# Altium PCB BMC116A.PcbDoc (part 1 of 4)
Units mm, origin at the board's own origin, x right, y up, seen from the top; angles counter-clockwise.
Board outline 154.94 x 104.14 mm, 6 copper layers (Top Layer, Signal Layer 1, Signal Layer 2, Signal Layer 3, Signal Layer 4, Bottom Layer), stack 1.56 mm thick; 252 components, 114 nets, 652 pads, 2530 vias.
Unrouted connection lines stored in the file: 13.
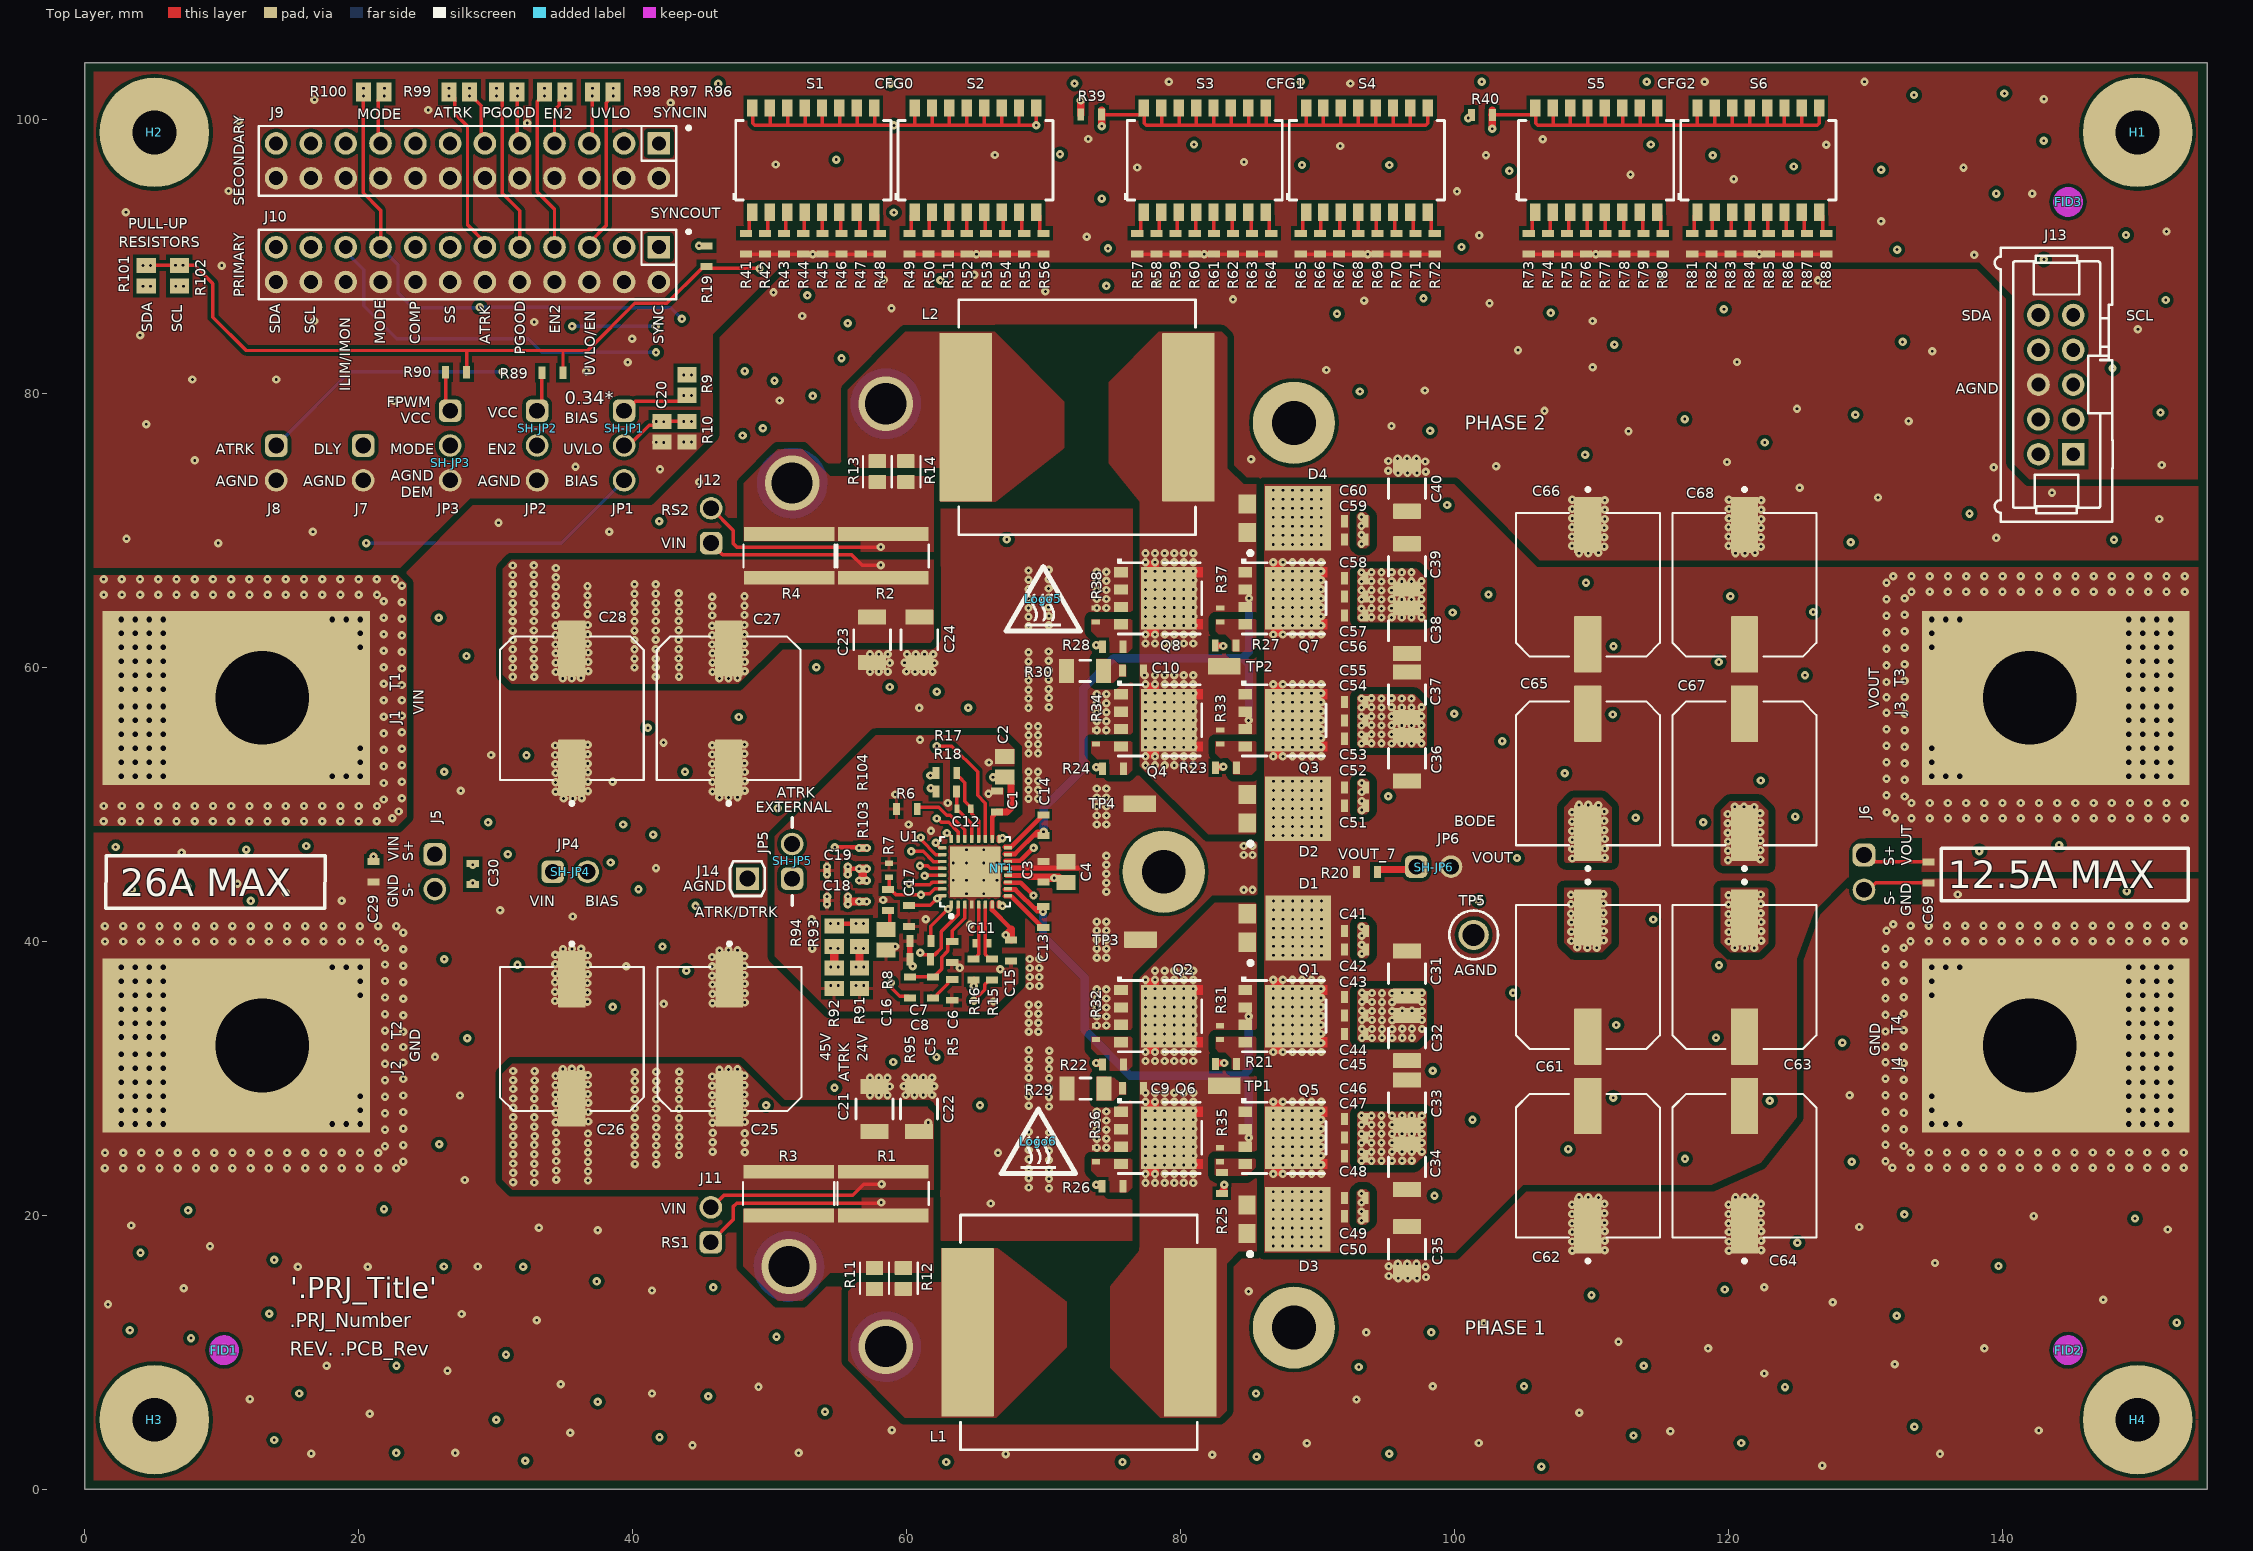
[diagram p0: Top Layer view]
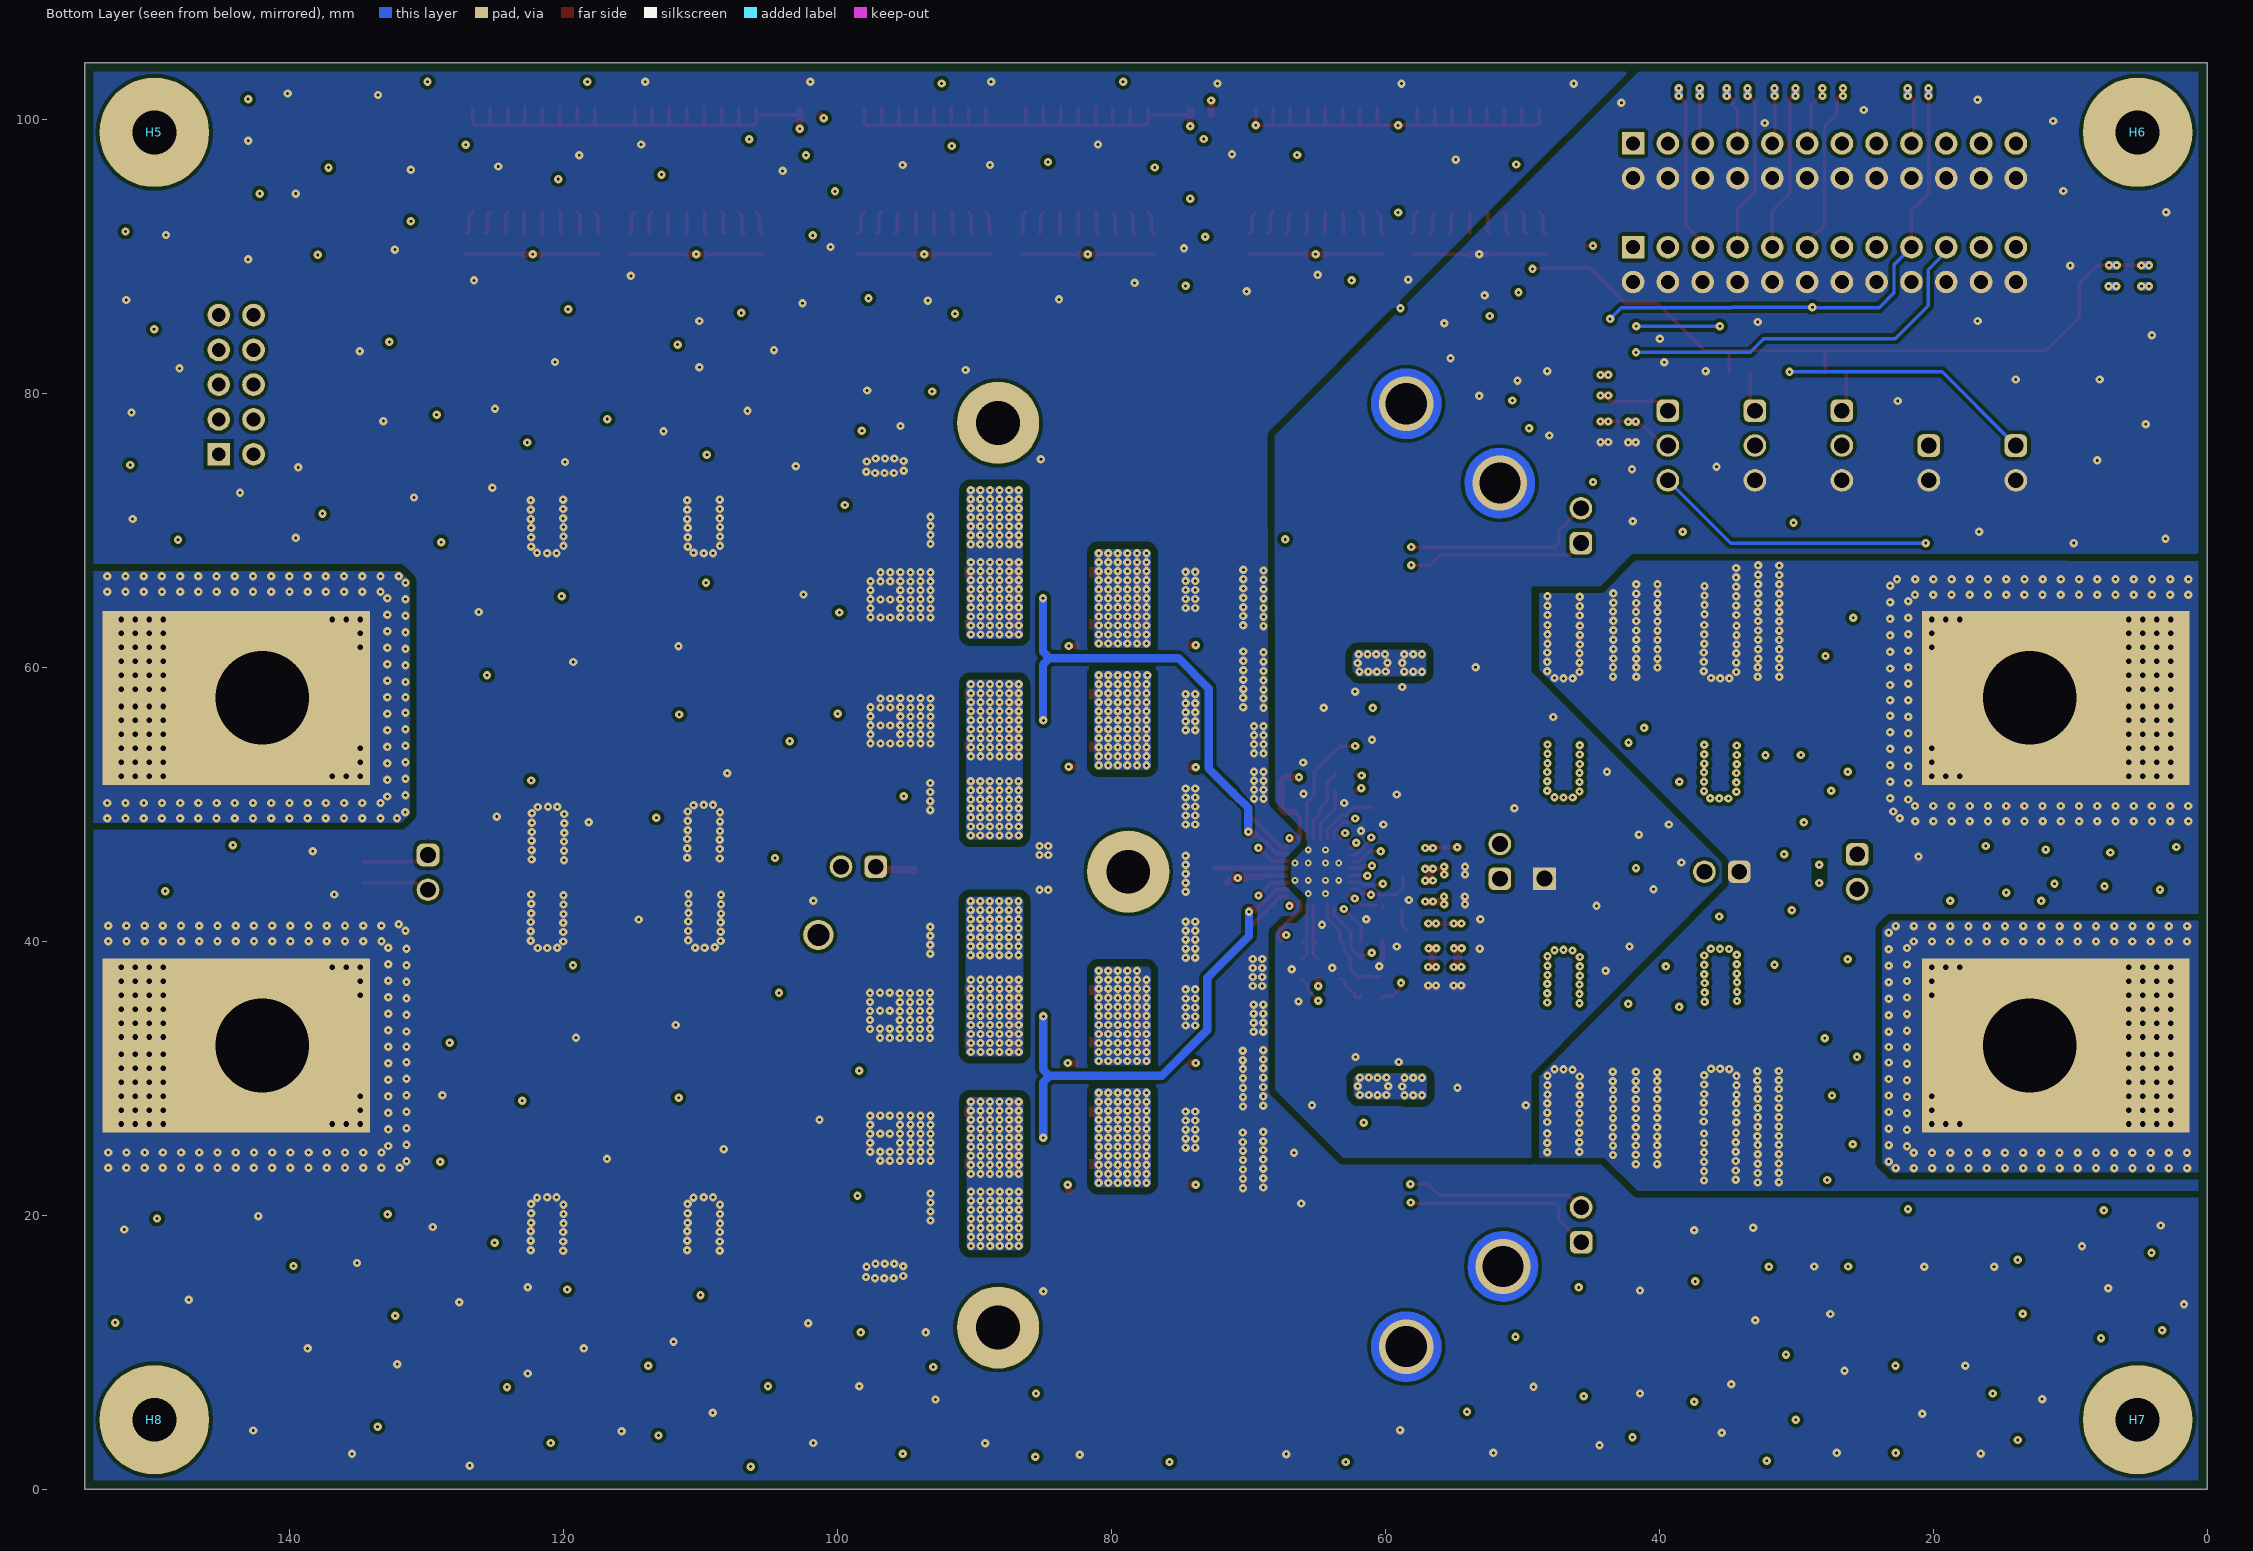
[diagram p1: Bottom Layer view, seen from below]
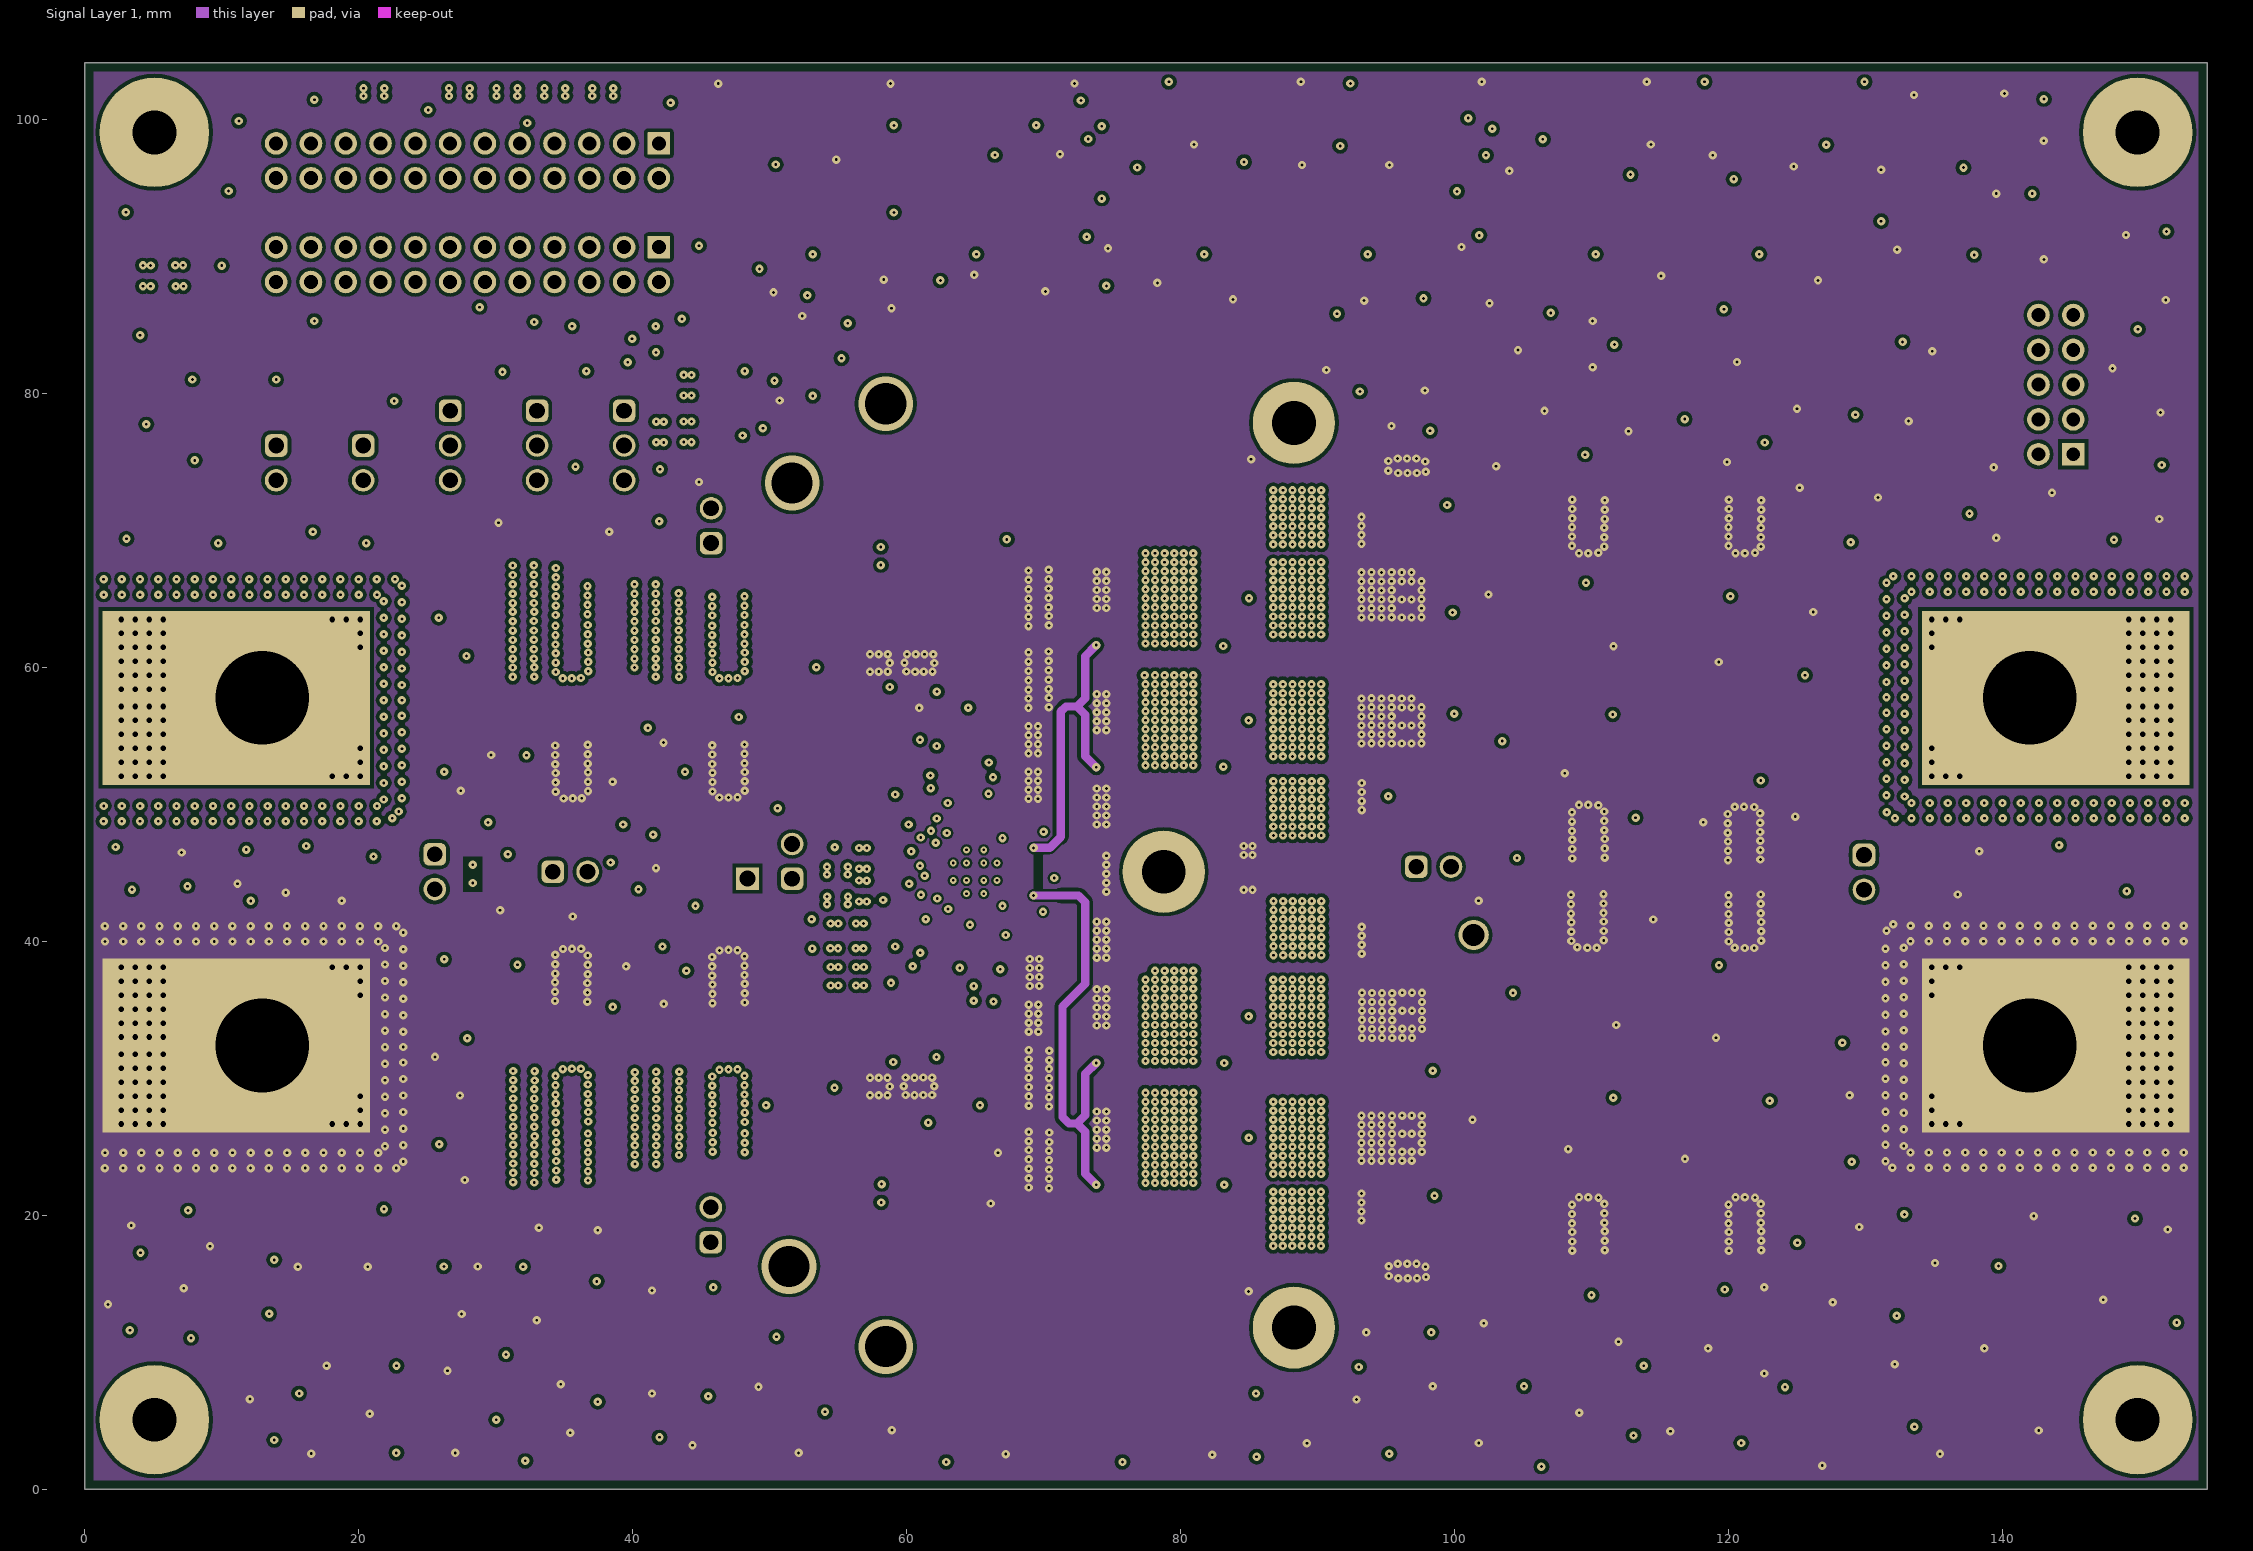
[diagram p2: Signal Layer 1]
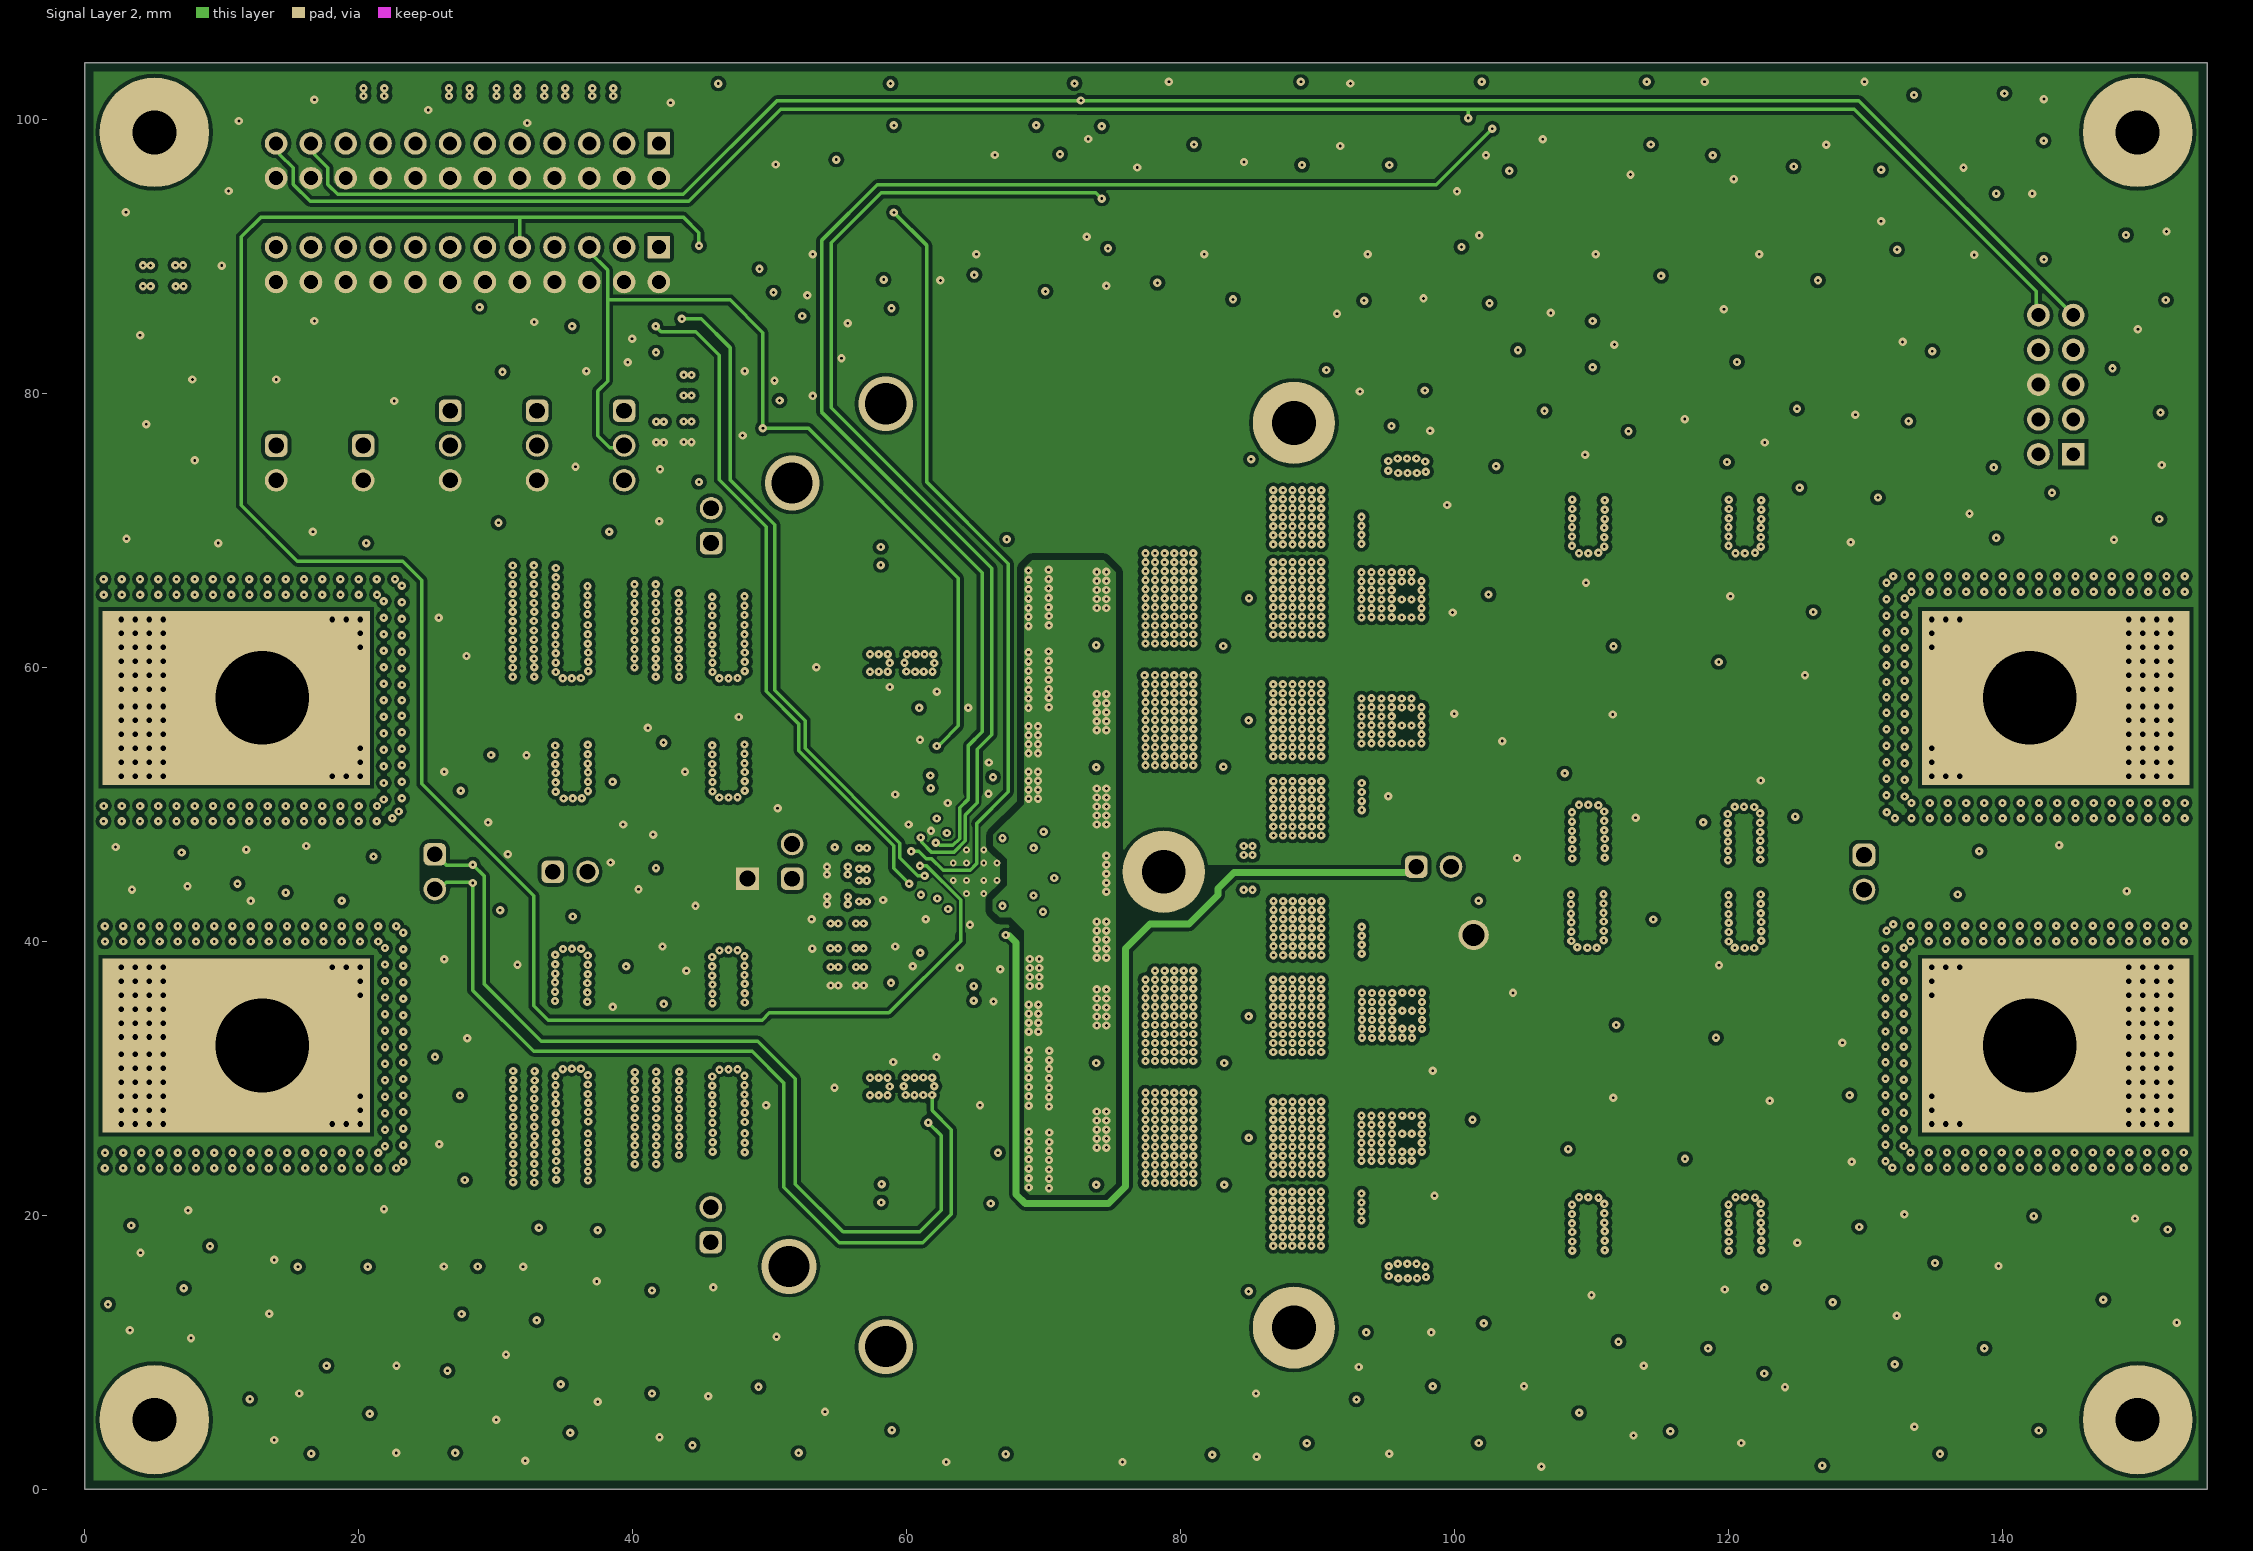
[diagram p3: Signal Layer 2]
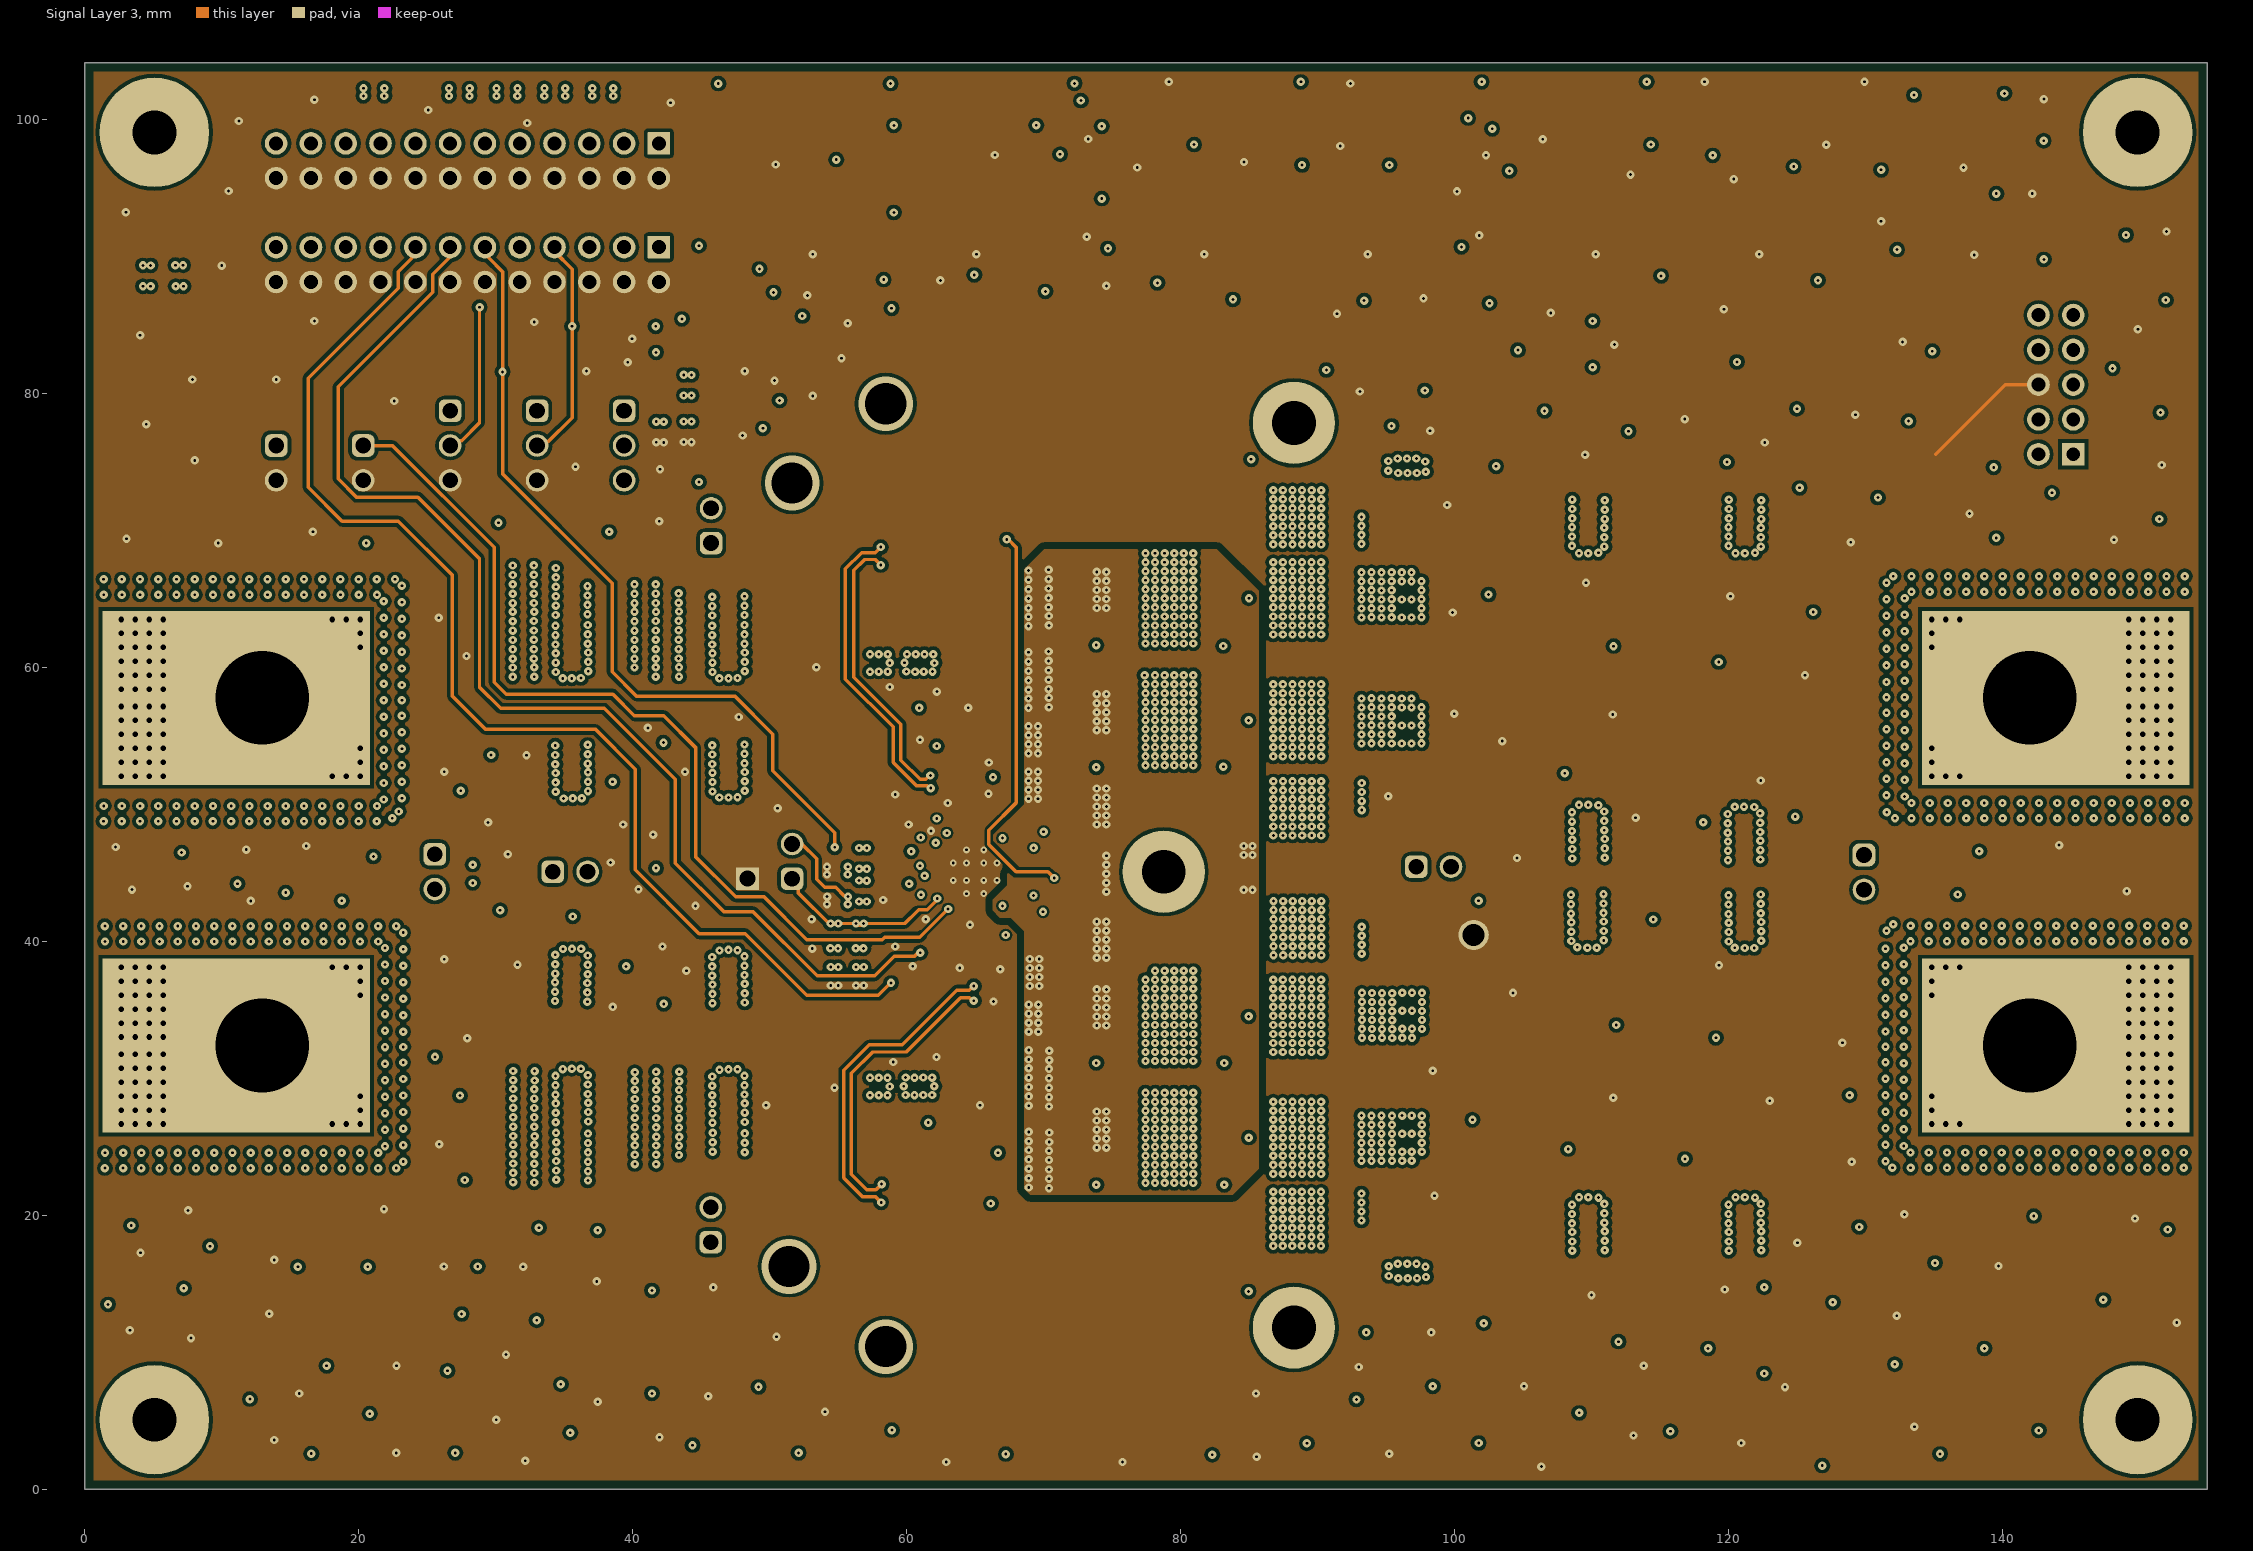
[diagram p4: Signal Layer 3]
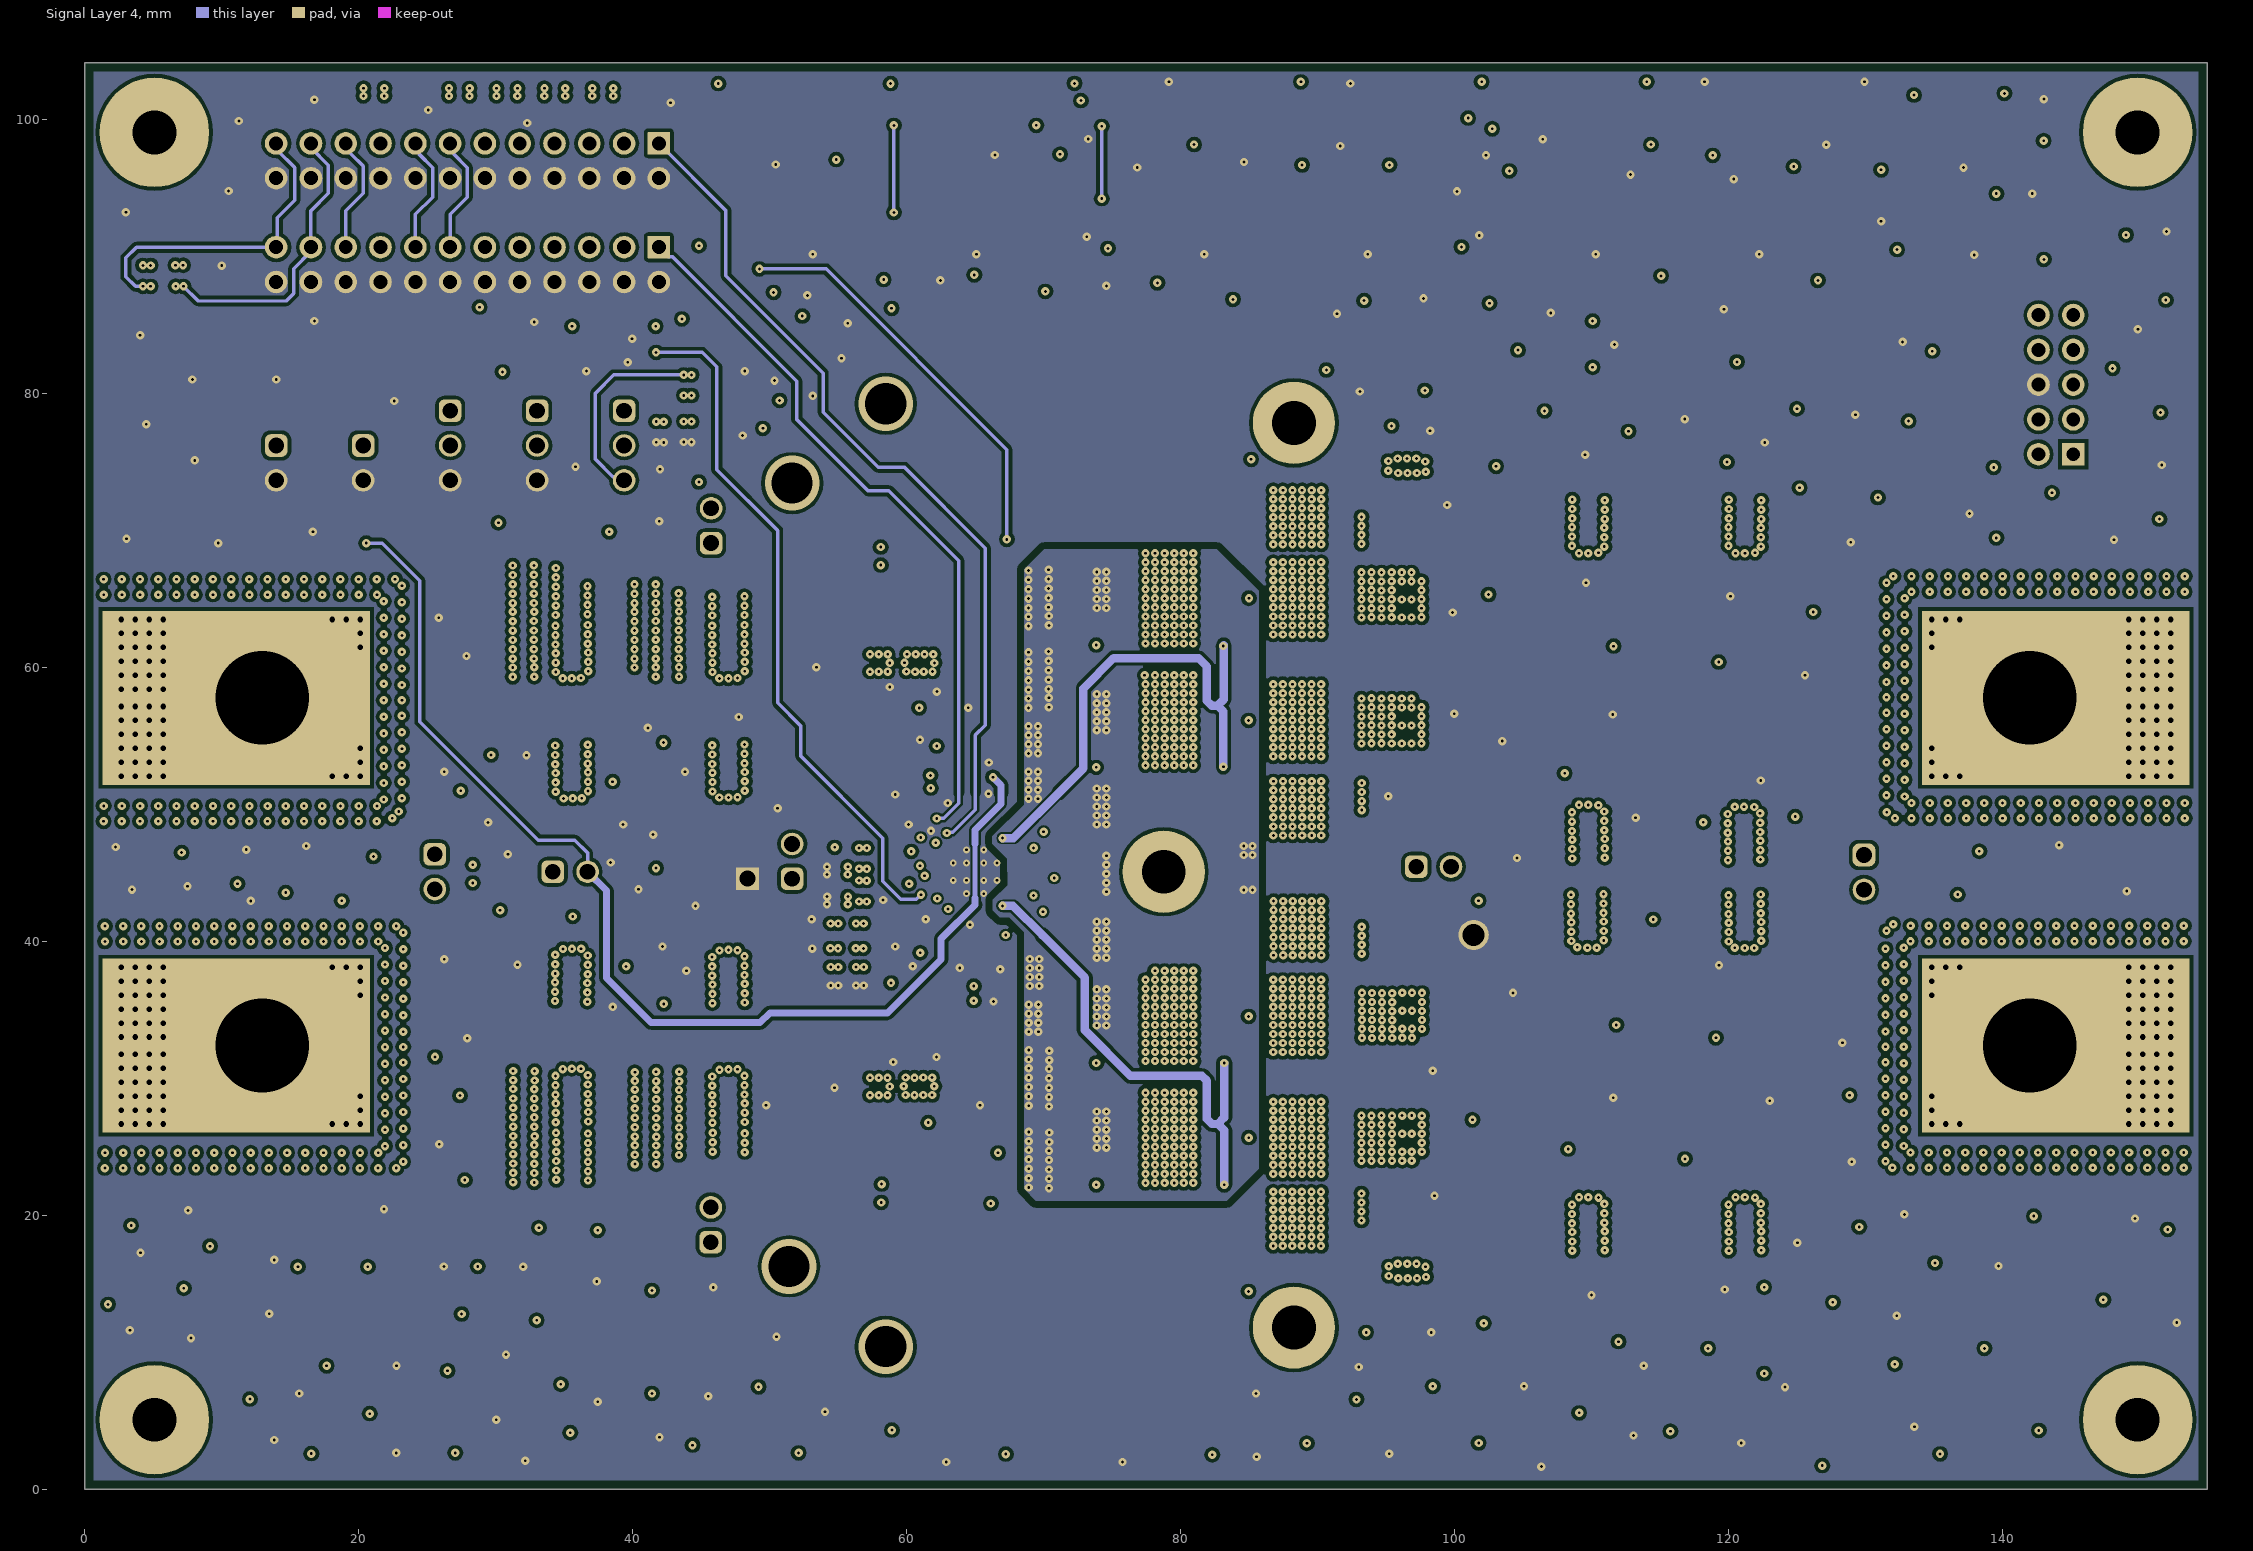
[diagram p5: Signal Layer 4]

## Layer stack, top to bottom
Top Solder: solder mask 0.0127, Solder Resist, Dk 3.5
Top Layer: signal copper 0.0711
Dielectric 1: prepreg 0.1778, FR-4 High Tg, Dk 4.2
Signal Layer 1: signal copper 0.0356
Dielectric 2: core 0.3556, FR-4 High Tg, Dk 4.2
Signal Layer 2: signal copper 0.0356
Dielectric 4: prepreg 0.2083, FR-4 High Tg, Dk 4.2
Signal Layer 3: signal copper 0.0356
Dielectric 5: core 0.3556, FR-4 High Tg, Dk 4.2
Signal Layer 4: signal copper 0.0356
Dielectric 3: prepreg 0.1778, FR-4 High Tg, Dk 4.2
Bottom Layer: signal copper 0.0711
Bottom Solder: solder mask 0.0127, Solder Resist, Dk 3.5

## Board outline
0,0 154.94,0 154.94,104.14 0,104.14

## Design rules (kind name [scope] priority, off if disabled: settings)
AcuteAngle [All] p1: minimum=4.50000000000000E+0001 checktracksonly=FALSE
AssemblyTestPointUsage [All] p1: valid=2
BoardOutlineClearance BoardOutlineClearance_MountingHoles [OnCopper and InComponentClass('Mounting Holes')] p1: gap=1 ignorepadtopadclearanceinfootprint=FALSE
BoardOutlineClearance BoardOutlineClearance_Poly [OnCopper and IsPoly] p2: gap=0.635 ignorepadtopadclearanceinfootprint=FALSE
BoardOutlineClearance [OnCopper and Not InComponentClass('Logo') and not InComponentClass('FiducialMark') and not InRegion(1000,500,4000,800) and not InPoly] p3: gap=1.016 ignorepadtopadclearanceinfootprint=FALSE
Clearance Clearance_IC [WithinRoom('IC_Room')] p1: gap=0.152 ignorepadtopadclearanceinfootprint=TRUE
Clearance Clearance_Keepouts [((IsTrack Or IsArc) And Not InPoly) And IsFree and IsKeepOut vs ((IsTrack Or IsArc) And Not InPoly) And IsFree and IsKeepOut] p2: gap=0 ignorepadtopadclearanceinfootprint=FALSE
Clearance Clearance_Poly [InPolygon] p3: gap=0.254 ignorepadtopadclearanceinfootprint=TRUE except(0.508: Poly-Poly)
Clearance Clearance_FiducialMark [IsKeepOut and InComponentClass('FiducialMark') vs IsPad and InComponentClass('FiducialMark')] p4: gap=0 ignorepadtopadclearanceinfootprint=FALSE
Clearance [All] p5: gap=0.2 ignorepadtopadclearanceinfootprint=TRUE
ComponentClearance ComponentClearance_Banana [HasFootprint('Johnson_108-0740-001') vs HasFootprint('Panduit_CXS70-14-C')] p1: gap=-1 collisioncheckmode=3 verticalgap=0 showdistances=FALSE
ComponentClearance ComponentClearance_JP_Res [InComponent('JP6') or InComponent('JP7') or InComponent('R1') or InComponent('R2') or InComponent('R3') or InComponent('R4') or InComponent('R11') or InComponent('R13') or InComponent('J11') or InComponent('J12') or  InComponent('J27') or InComponent('J28')] p2: gap=0 collisioncheckmode=3 verticalgap=0 showdistances=FALSE
ComponentClearance ComponentClearance_NT [InComponent('U1') or InComponent('NT1')] p3: gap=-1 collisioncheckmode=3 verticalgap=0 showdistances=FALSE
ComponentClearance ComponentClearance_MountingHoles_FiducialMarks [InComponentClass('Mounting Holes') vs InComponentClass('FiducialMark')] p4: gap=1.27 collisioncheckmode=3 verticalgap=0.254 showdistances=FALSE
ComponentClearance ComponentClearance_Shunt [InComponentClass('Header') vs InComponentClass('Shunt') or InComponent('SH-JP1') or InComponent('SH-JP2') or InComponent('SH-JP3') or InComponent('SH-JP4') or InComponent('SH-JP5') or InComponent('SH-JP6') or  InComponent('SH-JP8')  or  InComponent('SH-JP9')] p5: gap=0 collisioncheckmode=3 verticalgap=0 showdistances=FALSE
ComponentClearance ComponentClearance_Logo [InComponentClass('Logo')] p6: gap=0.762 collisioncheckmode=3 verticalgap=0.254 showdistances=FALSE
ComponentClearance ComponentClearance_ScrewToNut [(HasFootprint('NY PMS 440 0025 PH')) vs (HasFootprint('Keystone_1902C'))] p7: gap=0.127 collisioncheckmode=3 verticalgap=0.254 showdistances=FALSE
ComponentClearance ComponentClearance_MountingHoles [InComponentClass('Mounting Holes')] p8: gap=2.54 collisioncheckmode=3 verticalgap=2540 showdistances=FALSE
ComponentClearance ComponentClearance_SmallPassives [HasFootprint('0201*') or HasFootprint('0402*') or HasFootprint('0508') or HasFootprint('0603*') or HasFootprint('0612') or HasFootprint('0805*') or HasFootprint('0815*') or HasFootprint('0830*') or HasFootprint('1206*') or HasFootprint('1210*') or HasFootprint('1808*') or HasFootprint('1812*') or HasFootprint('1825*') or HasFootprint('2010*') or HasFootprint('2220*') or HasFootprint('2225*') or HasFootprint('2512*') or HasFootprint('2728*') or HasFootprint('3518*') vs HasFootprint('0201*') or HasFootprint('0402*') or HasFootprint('0508') or HasFootprint('0603*') or HasFootprint('0612') or HasFootprint('0805*') or HasFootprint('0815*') or HasFootprint('0830*') or HasFootprint('1206*') or HasFootprint('1210*') or HasFootprint('1808*') or HasFootprint('1812*') or HasFootprint('1825*') or HasFootprint('2010*') or HasFootprint('2220*') or HasFootprint('2225*') or HasFootprint('2512*') or HasFootprint('2728*') or HasFootprint('3518*')] p9: gap=0.38 collisioncheckmode=3 verticalgap=0.254 showdistances=FALSE
ComponentClearance ComponentClearance_THtoSMT [IsThruComponent vs IsSMTComponent] p10: gap=0.762 collisioncheckmode=3 verticalgap=0.762 showdistances=FALSE
ComponentClearance ComponentClearance_THtoTH [IsThruComponent vs IsThruComponent] p11: gap=0.508 collisioncheckmode=3 verticalgap=0.762 showdistances=FALSE
ComponentClearance [All] p12: gap=0.381 collisioncheckmode=3 verticalgap=0.254 showdistances=FALSE
DiffPairsRouting [All] p1: maxlimit=2.54 minlimit=0.254 mostfreqgap=0.254 toplayer_minwidth=0.381 toplayer_maxwidth=0.381 toplayer_prefwidth=0.381 midlayer1_minwidth=0.381 midlayer1_maxwidth=0.381 midlayer1_prefwidth=0.381 midlayer2_minwidth=0.381 midlayer2_maxwidth=0.381 midlayer2_prefwidth=0.381 midlayer3_minwidth=0.381 midlayer3_maxwidth=0.381 midlayer3_prefwidth=0.381 midlayer4_minwidth=0.381 midlayer4_maxwidth=0.381 midlayer4_prefwidth=0.381 bottomlayer_minwidth=0.381 bottomlayer_maxwidth=0.381 bottomlayer_prefwidth=0.381 maxuncoupledlength=25.4
FabricationTestPointUsage TestPointUsage [All] p1: valid=2 allowmultiple=FALSE
FabricationTestpoint Testpoint [All] p1: side=3 testpointundercomponent=TRUE minsize=1.016 maxsize=2.54 preferedsize=1.524 minholesize=0 maxholesize=1.016 preferedholesize=0.813 testpointgrid=0.025 allowsidetop=TRUE allowsidebottom=TRUE usegrid=TRUE gridtolerance=0
FanoutControl Fanout_LCC [IsLCC] p1: bgadir=Out bgaviamode=Centered fanoutstyle=Auto fanoutdirection=Alternating viagrid=0.025 // Fanout_LCC (Default Rule)
FanoutControl Fanout_BGA [IsBGA] p2: bgadir=Out bgaviamode=Centered fanoutstyle=Auto fanoutdirection=Alternating viagrid=0.025 // Fanout_BGA (Default Rule)
FanoutControl Fanout_Default [All] p4: bgadir=Out bgaviamode=Centered fanoutstyle=Auto fanoutdirection=Alternating viagrid=0.025 // Fanout_Default (Default Rule)
FanoutControl Fanout_Small [(CompPinCount < 5)] p5: bgadir=Out bgaviamode=Centered fanoutstyle=Auto fanoutdirection=OutThenIn viagrid=0.025 // Fanout_Small (Default Rule)
HoleSize [All] p1: absolutevalues=TRUE maxlimit=6.858 minlimit=0.2 maxpercent=80.000 minpercent=20.000
HoleToHoleClearance HoleToHoleClearance_Banana [HasFootprint('Johnson_108-0740-001') vs HasFootprint('Panduit_CXS70-14-C')] p1: gap=0 allowstackedmicrovias=TRUE
HoleToHoleClearance [All] p2: gap=0.254 allowstackedmicrovias=TRUE
MinimumAnnularRing MinimumAnnularRing_ThermalPadVias [IsVia and InAnyComponent] p1: minimumring=0.15
MinimumAnnularRing [All] p2: minimumring=0.2
MinimumSolderMaskSliver MinimumSolderMaskSliver_Logo [InComponentClass('Logo') vs InComponentClass('Logo')] p1: minsoldermaskwidth=0.018
MinimumSolderMaskSliver [All] p2: minsoldermaskwidth=0.1
PlaneConnect [All] p1: planeconnectstyle=Direct reliefexpansion=0.254 reliefentries=4 reliefconductorwidth=0.254 reliefairgap=0.254
PolygonConnect PolygonConnect_solder [InComponent('R5') or InComponent('R6') or InComponent('R7') or InComponent('R91') or InComponent('R92') or InComponent('C6') or InComponent('C7') or InComponent('C8') or InComponent('C15') or InComponent('C16') or InComponent('C17') or InComponent('C18') or InComponent('C19')] p1: connectstyle=Relief reliefconductorwidth=0.254 reliefentries=4 polygonreliefangle="90 Angle" airgapwidth=0.254
PolygonConnect [All] p2: connectstyle=Direct reliefconductorwidth=0.254 reliefentries=4 polygonreliefangle="90 Angle" airgapwidth=0.254
RoomDefinition IC_Room [InComponentClass('Top Side Components')] p1: confinementstyle=ConfineIn formatcopy=TRUE lockcomponents=FALSE outline 60.761,50.841 71.247,50.841 71.247,40.452 60.761,40.452
RoutingVias ThermalPadVias [IsVia and InAnyComponent] p1: holewidth=0.2 width=0.5 viastyle="Through Hole" minholewidth=0.2 minwidth=0.406 maxholewidth=0.406 maxwidth=0.813
RoutingVias [All] p2: holewidth=0.406 width=0.864 viastyle="Through Hole" minholewidth=0.2 minwidth=0.61 maxholewidth=6.858 maxwidth=6.858
SilkToBoardRegionClearance [Not ((IsComment or IsDesignator) And (Hide <> 'False')) and not InRegion(1000,500,4000,800)] p1:
SilkToSilkClearance SilkToSilkClearance_Pb-FreeLogo [(HasFootprint('Pb-Free_Overlay_Medium') OR HasFootprint('Pb-Free_Overlay_Small')) vs (HasFootprint('Pb-Free_Overlay_Medium') OR HasFootprint('Pb-Free_Overlay_Small'))] p1: silktosilkclearance=0
SilkToSilkClearance [All] p2: silktosilkclearance=0.1
SilkToSolderMaskClearance SilkToComponentPadClearance [(IsPad or IsFill or IsRegion) and InAnycomponent] p1: minsilkscreentomaskgap=0.127 clearancetoexposedcopper=TRUE
SilkToSolderMaskClearance "Silk to Solder Mask Opening" [All] p2: minsilkscreentomaskgap=0.1 clearancetoexposedcopper=FALSE
SolderMaskExpansion [All] p1: expansion=0.05 istentingtop=FALSE
SupplyNets "Schematic Supply Nets_1" [InNet('AGND')] p1: voltage=0.000
SupplyNets "Schematic Supply Nets" [InNet('GND')] p2: voltage=0.000
UnRoutedNet [All] p1: checkbadconnections=TRUE
Width [All] p1: maxlimit=2.54 minlimit=0.152 preferedwidth=0.254 checkconnectedcopper=TRUE
13 further rules are at their usual default settings.

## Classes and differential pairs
component class Shunt: SH-JP1 SH-JP2 SH-JP3 SH-JP4 SH-JP5 SH-JP6
component class Header: J5 J6 J7 J8 J9 J10 J11 J12 J14 JP1 JP2 JP3 JP4 JP5 JP6
component class BMC116A: C1 C2 C3 C4 C5 C6 C7 C8 C9 C10 C11 C12 C13 C14 C15 C16 C17 C18 C19 C20 C21 C22 C23 C24 C25 C26 C27 C28 C29 C30 C31 C32 C33 C34 C35 C36 C37 C38 C39 C40 C41 C42 C43 C44 C45 C46 C47 C48 C49 C50 C51 C52 C53 C54 C55 C56 C57 C58 C59 C60 C61 C62 C63 C64 C65 C66 C67 C68 C69 D1 D2 D3 D4 J1 J2 J3 J4 J5 J6 J7 J8 J9 J10 J11 J12 J13 J14 JP1 JP2 JP3 JP4 JP5 JP6 L1 L2 NT1 Q1 Q2 Q3 Q4 Q5 Q6 Q7 Q8 R1 R2 R3 R4 R5 R6 R7 R8 R9 R10 R11 R12 R13 R14 R15 R16 R17 R18 R19 R20 R21 R22 R23 R24 R25 R26 R27 R28 R29 R30 R31 R32 R33 R34 R35 R36 R37 R38 R39 R40 R41 R42 R43 R44 R45 R46 R47 R48 R49 R50 R51 R52 R53 R54 R55 R56 R57 R58 R59 R60 R61 R62 R63 R64 R65 R66 R67 R68 R69 R70 R71 R72 R73 R74 R75 R76 R77 R78 R79 R80 R81 R82 R83 R84 R85 R86 R87 R88 R89 R90 R91 R92 R93 R94 R95 R96 R97 R98 R99 R100 R101 R102 R103 R104 S1 S2 S3 S4 S5 S6 SH-JP1 SH-JP2 SH-JP3 SH-JP4 SH-JP5 SH-JP6 T1 T2 T3 T4 TP1 TP2 TP3 TP4 TP5 U1
component class "Mounting Holes": H1 H2 H3 H4
component class BMC116A_Hardware: FID1 FID2 FID3 H1 H2 H3 H4 H5 H6 H7 H8 Logo5 Logo6 ZZ2 ZZ3 ZZ4 ZZ5 ZZ6 ZZ7 ZZ8 ZZ9 ZZ10
component class FiducialMark: FID1 FID2 FID3
component class AssemblyNote: ZZ2 ZZ3 ZZ4 ZZ5 ZZ6 ZZ7 ZZ8 ZZ9 ZZ10

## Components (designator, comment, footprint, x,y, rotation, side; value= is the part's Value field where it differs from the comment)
C1 "GRM188R72A104KA35D" 0603S 66.599,50.217 r90 top value=0.1uF
C2 "GCM21BR71H105KA03K" 0805L 67.164,52.738 r270 top value=1uF
C3 "GRM188R72A104KA35D" 0603S 69.996,45.085 r90 top value=0.1uF
C4 "GCJ21BR71A106KE01L" 0805L 71.622,45.066 r90 top value=10uF
C5 "GCM188R72A153KA37D" 0603S 61.923,36.629 r270 top value=0.015uF
C6 "CC0603JRNPO9BN501" 0603S 63.324,39.221 r270 top value=500pF
C7 "C1608C0G1H100D080AA" 0603S 61.003,40.027 r180 top value=10pF
C8 "C0603C334K8PACTU" 0603S 60.99,38.693 r180 top value=0.33uF
C9 "C0603C681K5RACTU" 0603S 76.522,29.283 r180 top value=680pF
C10 "C0603C681K5RACTU" 0603S 76.518,59.766 r180 top value=680pF
C11 "04025A680FAT2A" 0402S 65.492,39.861 r180 top value=68pF
C12 "04025A680FAT2A" 0402S 64.175,49.696 r0 top value=68pF
C13 "GRM188R72A104KA35D" 0603S 69.972,41.782 r270 top value=0.1uF
C14 "GRM188R72A104KA35D" 0603S 69.996,48.479 r270 top value=0.1uF
C15 "GRM188R72A104KA35D" 0603S 67.609,39.344 r270 top value=0.1uF
C16 "C2012X7R1E335K125AB" 0805L 58.48,40.13 r270 top value=3.3uF
C17 "C1608C0G1H101J080AE" 0603S 60.177,41.865 r270 top value=100pF
C18 "C1608X7R1H473K080AA" 0603S 54.947,42.99 r180 top value=0.047uF
C19 "C1608X7R1H473K080AA" 0603S 54.942,45.166 r180 top value=0.047uF
C20 "CGA4J2X7R2A104K125AA" 0805L 42.127,77.208 r270 top value=0.1uF
C21 "GRM32EC72A106KE05L" FP-GRM32EC72A106KE05L_1210-MFG 57.649,27.768 r270 top
C22 "GRM32EC72A106KE05L" FP-GRM32EC72A106KE05L_1210-MFG 60.902,27.768 r270 top
C23 "GRM32EC72A106KE05L" FP-GRM32EC72A106KE05L_1210-MFG 57.476,62.025 r90 top
C24 "GRM32EC72A106KE05L" FP-GRM32EC72A106KE05L_1210-MFG 60.926,62.025 r90 top
C25 "EEHZU1H221P" FP-EEHZU1H221P_RADIAL_SMT-MFG 47.06,32.881 r270 top value=220µF
C26 "EEHZU1H221P" FP-EEHZU1H221P_RADIAL_SMT-MFG 35.555,32.881 r270 top value=220µF
C27 "EEHZU1H221P" FP-EEHZU1H221P_RADIAL_SMT-MFG 47.005,57.023 r90 top value=220µF
C28 "EEHZU1H221P" FP-EEHZU1H221P_RADIAL_SMT-MFG 35.555,57.023 r90 top value=220µF
C29 "GRM188R72A104KA35D" 0603S 21.082,45.085 r270 top value=0.1uF
C30 "GRM188R72A104KA35D" 0603S 28.316,44.926 r270 top value=0.1uF
C31 "GRM32EC72A106KE05L" FP-GRM32EC72A106KE05L_1210-MFG 96.52,37.651 r90 top
C32 "GRM32EC72A106KE05L" FP-GRM32EC72A106KE05L_1210-MFG 96.52,32.941 r270 top
C33 "GRM32EC72A106KE05L" FP-GRM32EC72A106KE05L_1210-MFG 96.52,28.23 r90 top
C34 "GRM32EC72A106KE05L" FP-GRM32EC72A106KE05L_1210-MFG 96.52,23.54 r270 top
C35 "GRM32EC72A106KE05L" FP-GRM32EC72A106KE05L_1210-MFG 96.531,17.523 r90 top
C36 "GRM32EC72A106KE05L" FP-GRM32EC72A106KE05L_1210-MFG 96.52,53.361 r270 top
C37 "GRM32EC72A106KE05L" FP-GRM32EC72A106KE05L_1210-MFG 96.52,58.011 r90 top
C38 "GRM32EC72A106KE05L" FP-GRM32EC72A106KE05L_1210-MFG 96.52,62.675 r270 top
C39 "GRM32EC72A106KE05L" FP-GRM32EC72A106KE05L_1210-MFG 96.52,67.379 r90 top
C40 "GRM32EC72A106KE05L" FP-GRM32EC72A106KE05L_1210-MFG 96.52,73.053 r270 top
C41 "GRM188R72A104KA35D" 0603S 92.725,40.756 r0 top value=0.1uF
C42 "GRM188R72A104KA35D" 0603S 92.725,39.417 r0 top value=0.1uF
C43 "GRM188R72A104KA35D" 0603S 92.71,35.93 r0 top value=0.1uF
C44 "GRM188R72A104KA35D" 0603S 92.71,34.582 r0 top value=0.1uF
C45 "GRM188R72A104KA35D" 0603S 92.71,33.242 r0 top value=0.1uF
C46 "GRM188R72A104KA35D" 0603S 92.71,27.039 r0 top value=0.1uF
C47 "GRM188R72A104KA35D" 0603S 92.71,25.675 r0 top value=0.1uF
C48 "GRM188R72A104KA35D" 0603S 92.71,24.313 r0 top value=0.1uF
C49 "GRM188R72A104KA35D" 0603S 92.71,21.278 r0 top value=0.1uF
C50 "GRM188R72A104KA35D" 0603S 92.71,19.94 r0 top value=0.1uF
C51 "GRM188R72A104KA35D" 0603S 92.726,49.903 r0 top value=0.1uF
C52 "GRM188R72A104KA35D" 0603S 92.726,51.241 r0 top value=0.1uF
C53 "GRM188R72A104KA35D" 0603S 92.71,54.792 r0 top value=0.1uF
C54 "GRM188R72A104KA35D" 0603S 92.71,56.127 r0 top value=0.1uF
C55 "GRM188R72A104KA35D" 0603S 92.71,57.478 r0 top value=0.1uF
C56 "GRM188R72A104KA35D" 0603S 92.71,63.802 r0 top value=0.1uF
C57 "GRM188R72A104KA35D" 0603S 92.71,65.178 r0 top value=0.1uF
C58 "GRM188R72A104KA35D" 0603S 92.71,66.512 r0 top value=0.1uF
C59 "GRM188R72A104KA35D" 0603S 92.71,69.335 r0 top value=0.1uF
C60 "GRM188R72A104KA35D" 0603S 92.71,70.674 r0 top value=0.1uF
C61 "EEHZU1J151P" FP-EEHZU1J151P_RADIAL_SMT-MFG 109.728,37.395 r270 top value=150µF
C62 "EEHZU1J151P" FP-EEHZU1J151P_RADIAL_SMT-MFG 109.729,23.622 r90 top value=150µF
C63 "EEHZU1J151P" FP-EEHZU1J151P_RADIAL_SMT-MFG 121.158,37.395 r270 top value=150µF
C64 "EEHZU1J151P" FP-EEHZU1J151P_RADIAL_SMT-MFG 121.158,23.622 r90 top value=150µF
C65 "EEHZU1J151P" FP-EEHZU1J151P_RADIAL_SMT-MFG 109.728,52.267 r90 top value=150µF
C66 "EEHZU1J151P" FP-EEHZU1J151P_RADIAL_SMT-MFG 109.728,66.04 r270 top value=150µF
C67 "EEHZU1J151P" FP-EEHZU1J151P_RADIAL_SMT-MFG 121.158,52.267 r90 top value=150µF
C68 "EEHZU1J151P" FP-EEHZU1J151P_RADIAL_SMT-MFG 121.158,66.04 r270 top value=150µF
C69 "GRM188R72A104KA35D" 0603S 134.6,45.03 r270 top value=0.1uF
D1 "V12P10-M3/86A" TO-277A 86.701,40.979 r90 top value=100V
D2 "V12P10-M3/86A" TO-277A 86.688,49.684 r90 top value=100V
D3 "V12P10-M3/86A" TO-277A 86.672,19.721 r90 top value=100V
D4 "V12P10-M3/86A" TO-277A 86.685,70.897 r90 top value=100V
FID1 "Fiducial" Fiducial10-20 10.16,10.16 r0 top
FID2 "Fiducial" Fiducial10-20 144.78,10.16 r0 top
FID3 "Fiducial" Fiducial10-20 144.78,93.98 r0 top
H1 "NY PMS 440 0025 PH" "NY PMS 440 0025 PH" 149.86,99.06 r0 top
H2 "NY PMS 440 0025 PH" "NY PMS 440 0025 PH" 5.08,99.06 r0 top
H3 "NY PMS 440 0025 PH" "NY PMS 440 0025 PH" 5.08,5.08 r0 top
H4 "NY PMS 440 0025 PH" "NY PMS 440 0025 PH" 149.86,5.08 r0 top
H5 "1902C" Keystone_1902C 149.86,99.06 r180 bottom
H6 "1902C" Keystone_1902C 5.08,99.06 r180 bottom
H7 "1902C" Keystone_1902C 5.08,5.08 r180 bottom
H8 "1902C" Keystone_1902C 149.86,5.08 r180 bottom
J1 "108-0740-001" Johnson_108-0740-001 12.954,57.785 r0 top
J2 "108-0740-001" Johnson_108-0740-001 12.954,32.385 r0 top
J3 "108-0740-001" Johnson_108-0740-001 141.986,57.785 r0 top
J4 "108-0740-001" Johnson_108-0740-001 141.986,32.385 r0 top
J5 "61300211121" WURTH_61300211121 25.552,45.085 r270 top
J6 "61300211121" WURTH_61300211121 129.885,45.038 r270 top
J7 "61300211121" WURTH_61300211121 20.32,74.93 r270 top
J8 "61300211121" WURTH_61300211121 13.97,74.93 r270 top
J9 "TSW-112-07-G-D" TSW-112-07-G-D 27.94,96.985 r180 top
J10 "TSW-112-07-G-D" TSW-112-07-G-D 27.94,89.408 r180 top
J11 "61300211121" WURTH_61300211121 45.702,19.315 r90 top
J12 "61300211121" WURTH_61300211121 45.72,70.346 r90 top
J13 "Header_5x2" CONN_2510-6002 143.891,80.645 r90 top
J14 "61300111121" WURTH_61300111121 48.376,44.588 r0 top
JP1 "61300311121" WURTH_61300311121 39.37,76.2 r270 top
JP2 "61300311121" WURTH_61300311121 33.02,76.2 r270 top
JP3 "61300311121" WURTH_61300311121 26.67,76.2 r270 top
JP4 "61300211121" WURTH_61300211121 35.433,45.085 r0 top
JP5 "61300211121" WURTH_61300211121 51.636,45.841 r90 top
JP6 "61300211121" WURTH_61300211121 98.464,45.457 r0 top
L1 "IHLP6767GZER3R3M5A" IHLP-6767GZ 72.569,11.459 r180 top value=3.3uH
L2 "IHLP6767GZER3R3M5A" IHLP-6767GZ 72.44,78.27 r0 top value=3.3uH
Logo5 "CAUTION HOT SURFACE" IEC_HotSurface_Small 69.972,65.024 r0 top
Logo6 "CAUTION HOT SURFACE" IEC_HotSurface_Small 69.614,25.409 r0 top
NT1 "Net-Tie" Net-Tie_10milWide_30milLong 66.942,45.337 r0 top net-tie
Q1 "NTM" SO-8FL 87.503,34.544 r0 top value=60V
Q2 "NTM" SO-8FL 78.435,34.544 r0 top value=60V
Q3 "NTM" SO-8FL 87.503,56.134 r0 top value=60V
Q4 "NTM" SO-8FL 78.435,56.134 r0 top value=60V
Q5 "NTM" SO-8FL 87.503,25.654 r0 top value=60V
Q6 "NTM" SO-8FL 78.435,25.654 r0 top value=60V
Q7 "NTM" SO-8FL 87.503,65.049 r0 top value=60V
Q8 "NTM" SO-8FL 78.435,65.049 r0 top value=60V
R1 "PML100HZPJV1L5" 2512_WIDE 58.293,21.59 r90 top value=0.0015
R2 "PML100HZPJV1L5" 2512_WIDE 58.292,68.148 r90 top value=0.0015
R3 "PML100HZPJV1L5" 2512_WIDE 51.395,21.59 r90 top value=0.0015
R4 "PML100HZPJV1L5" 2512_WIDE 51.431,68.148 r90 top value=0.0015
R5 "CRCW060320K0FKEA" 0603S 63.325,36.467 r90 top value=20.0k
R6 "RT0603BRD0778K7L" 0603S 60.01,49.666 r0 top value=78.7k
R7 "CRCW040247K5FKED" 0402S 58.714,45.197 r270 top value=47.5k
R8 "CRCW06036K04FKEA" 0603S 58.628,43.024 r90 top value=6.04k
R9 "CRCW080575K0FKEA" 0805L 43.967,80.618 r270 top value=75.0k
R10 "CRCW080539K0JNEA" 0805L 43.967,77.218 r270 top value=39k
R11 "WSL080500000ZEA9" FP-WSL080500000ZEA9_0805-MFG 57.649,15.398 r90 top value=0
R12 "WSL080500000ZEA9" FP-WSL080500000ZEA9_0805-MFG 59.759,15.398 r90 top value=0
R13 "WSL080500000ZEA9" FP-WSL080500000ZEA9_0805-MFG 57.861,74.297 r90 top value=0
R14 "WSL080500000ZEA9" FP-WSL080500000ZEA9_0805-MFG 59.944,74.297 r90 top value=0
R15 "RMCF0603ZT0R00" 0603S 66.233,37.951 r270 top value=0
R16 "RMCF0603ZT0R00" 0603S 64.888,37.951 r270 top value=0
R17 "RMCF0603ZT0R00" 0603S 62.893,52.3 r180 top value=0
R18 "RMCF0603ZT0R00" 0603S 62.888,50.947 r180 top value=0
R19 "CRCW0603100KFKEA" 0603S 45.388,90.015 r90 top value=100k
R20 "CRCW060310R0FKEA" 0603S 93.601,45.066 r0 top value=10.0
R21 "ERJ-3RQF2R2V" 0603S 83.322,31.051 r180 top value=2.20
R22 "CRCW060310R0FKEA" 0603S 75.063,31.012 r0 top value=10.0
R23 "ERJ-3RQF2R2V" 0603S 83.299,52.678 r0 top value=2.20
R24 "CRCW060310R0FKEA" 0603S 75.058,52.599 r180 top value=10.0
R25 "ERJ-3RQF2R2V" 0603S 83.013,22.37 r270 top value=2.20
R26 "CRCW060310R0FKEA" 0603S 75.02,22.122 r0 top value=10.0
R27 "ERJ-3RQF2R2V" 0603S 83.287,61.605 r0 top value=2.20
R28 "CRCW060310R0FKEA" 0603S 75.044,61.515 r180 top value=10.0
R29 "CRCW12063R24FKEA" 1206L 73.054,29.245 r0 top value=3.24
R30 "CRCW12063R24FKEA" 1206L 73.025,59.741 r0 top value=3.24
R31 "CRCW0402100KFKED" 0402S 82.873,33.341 r270 top value=100k
R32 "CRCW0402100KFKED" 0402S 73.82,33.341 r270 top value=100k
R33 "CRCW0402100KFKED" 0402S 82.89,54.917 r270 top value=100k
R34 "CRCW0402100KFKED" 0402S 73.82,54.917 r270 top value=100k
R35 "CRCW0402100KFKED" 0402S 82.873,24.425 r270 top value=100k
R36 "CRCW0402100KFKED" 0402S 73.82,24.425 r270 top value=100k
R37 "CRCW0402100KFKED" 0402S 82.89,63.829 r270 top value=100k
R38 "CRCW0402100KFKED" 0402S 73.797,63.829 r270 top value=100k
R39 "RMCF0603ZT0R00" 0603S 73.468,100.358 r0 top value=0
R40 "RMCF0603ZT0R00" 0603S 101.988,100.338 r0 top value=0
R41 "RMCF0603ZT0R00" 0603S 48.26,90.932 r270 top value=0
R42 "CRCW0603511RFKEA" 0603S 49.657,90.932 r90 top value=511
R43 "CRCW06031K30FKEA" 0603S 51.054,90.932 r270 top value=1.30k
R44 "CRCW06031K87FKEA" 0603S 52.451,90.932 r90 top value=1.87k
R45 "CRCW06032K74FKEA" 0603S 53.848,90.932 r270 top value=2.74k
R46 "CRCW06033K83FKEA" 0603S 55.245,90.932 r90 top value=3.83k
R47 "CRCW06035K11FKEA" 0603S 56.642,90.932 r90 top value=5.11k
R48 "CRCW06036K49FKEA" 0603S 58.039,90.932 r90 top value=6.49k
R49 "CRCW06038K25FKEA" 0603S 60.198,90.932 r90 top value=8.25k
R50 "CRCW060310K5FKEA" 0603S 61.595,90.932 r90 top value=10.5k
R51 "CRCW060313K3FKEA" 0603S 62.992,90.932 r90 top value=13.3k
R52 "CRCW060316K2FKEA" 0603S 64.389,90.932 r270 top value=16.2k
R53 "CRCW060320K5FKEA" 0603S 65.786,90.932 r90 top value=20.5k
R54 "CRCW060324K9FKEA" 0603S 67.183,90.932 r90 top value=24.9k
R55 "CRCW060330K1FKEA" 0603S 68.58,90.932 r90 top value=30.1k
R56 "CRCW060336K5FKEA" 0603S 69.977,90.932 r270 top value=36.5k
R57 "RMCF0603ZT0R00" 0603S 76.835,90.932 r270 top value=0
R58 "CRCW0603511RFKEA" 0603S 78.232,90.932 r90 top value=511
R59 "CRCW06031K30FKEA" 0603S 79.629,90.932 r270 top value=1.30k
R60 "CRCW06031K87FKEA" 0603S 81.026,90.932 r90 top value=1.87k
R61 "CRCW06032K74FKEA" 0603S 82.423,90.932 r270 top value=2.74k
R62 "CRCW06033K83FKEA" 0603S 83.82,90.932 r90 top value=3.83k
R63 "CRCW06035K11FKEA" 0603S 85.217,90.932 r90 top value=5.11k
R64 "CRCW06036K49FKEA" 0603S 86.614,90.932 r90 top value=6.49k
R65 "CRCW06038K25FKEA" 0603S 88.773,90.932 r90 top value=8.25k
R66 "CRCW060310K5FKEA" 0603S 90.17,90.932 r90 top value=10.5k
R67 "CRCW060313K3FKEA" 0603S 91.567,90.932 r90 top value=13.3k
R68 "CRCW060316K2FKEA" 0603S 92.964,90.932 r270 top value=16.2k
R69 "CRCW060320K5FKEA" 0603S 94.361,90.932 r90 top value=20.5k
R70 "CRCW060324K9FKEA" 0603S 95.758,90.932 r90 top value=24.9k
R71 "CRCW060330K1FKEA" 0603S 97.155,90.932 r90 top value=30.1k
R72 "CRCW060336K5FKEA" 0603S 98.552,90.932 r270 top value=36.5k
R73 "RMCF0603ZT0R00" 0603S 105.41,90.932 r270 top value=0
R74 "CRCW0603511RFKEA" 0603S 106.807,90.932 r90 top value=511
R75 "CRCW06031K30FKEA" 0603S 108.204,90.932 r270 top value=1.30k
R76 "CRCW06031K87FKEA" 0603S 109.601,90.932 r90 top value=1.87k
R77 "CRCW06032K74FKEA" 0603S 110.998,90.932 r270 top value=2.74k
R78 "CRCW06033K83FKEA" 0603S 112.395,90.932 r90 top value=3.83k
R79 "CRCW06035K11FKEA" 0603S 113.792,90.932 r90 top value=5.11k
R80 "CRCW06036K49FKEA" 0603S 115.189,90.932 r90 top value=6.49k
R81 "CRCW06038K25FKEA" 0603S 117.348,90.932 r90 top value=8.25k
R82 "CRCW060310K5FKEA" 0603S 118.745,90.932 r90 top value=10.5k
R83 "CRCW060313K3FKEA" 0603S 120.142,90.932 r90 top value=13.3k
R84 "CRCW060316K2FKEA" 0603S 121.539,90.932 r270 top value=16.2k
R85 "CRCW060320K5FKEA" 0603S 122.936,90.932 r90 top value=20.5k
R86 "CRCW060324K9FKEA" 0603S 124.333,90.932 r90 top value=24.9k
R87 "CRCW060330K1FKEA" 0603S 125.73,90.932 r90 top value=30.1k
R88 "CRCW060336K5FKEA" 0603S 127.127,90.932 r270 top value=36.5k
R89 "CRCW06034K99FKEA" 0603S 34.148,81.509 r0 top value=4.99k
R90 "CRCW06034K99FKEA" 0603S 27.109,81.555 r0 top value=4.99k
R91 "CRCW08050000Z0EA" 0805L 56.562,37.317 r90 top value=0
R92 "CRCW08050000Z0EA" 0805L 54.711,37.317 r90 top value=0
R93 "CRCW080540K2FKEA" 0805L 56.562,40.366 r90 top value=40.2k
R94 "CRCW080575K0FKEA" 0805L 54.711,40.366 r90 top value=75.0k
R95 "ERJ-3GEY0R00V" 0603S 60.243,36.637 r90 top value=0
R96 "CRCW08050000Z0EA" 0805L 37.806,102 r180 top value=0
R97 "CRCW08050000Z0EA" 0805L 34.309,102 r0 top value=0
R98 "CRCW08050000Z0EA" 0805L 30.812,102 r0 top value=0
R99 "CRCW08050000Z0EA" 0805L 27.34,102 r0 top value=0
R100 "CRCW08050000Z0EA" 0805L 21.1,102 r0 top value=0
R101 "CRCW080510K0FKEA" 0805L 4.484,88.586 r90 top locked value=10.0k
R102 "CRCW080510K0FKEA" 0805L 6.903,88.586 r90 top locked value=10.0k
R103 "CRCW06034K99FKEA" 0603S 56.805,43.679 r90 top value=4.99k
R104 "CRCW06034K99FKEA" 0603S 56.803,46.061 r90 top value=4.99k
S1 "218-8LPST" SW_218-8LP 53.185,97.028 r90 top
S2 "218-8LPST" SW_218-8LP 65.024,97.028 r90 top
S3 "218-8LPST" SW_218-8LP 81.76,97.028 r90 top
S4 "218-8LPST" SW_218-8LP 93.599,97.028 r90 top
S5 "218-8LPST" SW_218-8LP 110.335,97.028 r90 top
S6 "218-8LPST" SW_218-8LP 122.174,97.028 r90 top
SH-JP1 "SPC02SYAN" SPC02SYAN 39.37,77.47 r90 top value=1x2
SH-JP2 "SPC02SYAN" SPC02SYAN 33.02,77.47 r90 top value=1x2
SH-JP3 "SPC02SYAN" SPC02SYAN 26.67,74.93 r90 top value=1x2
SH-JP4 "SPC02SYAN" SPC02SYAN 35.433,45.085 r0 top value=1x2
SH-JP5 "SPC02SYAN" SPC02SYAN 51.628,45.877 r90 top value=1x2
SH-JP6 "SPC02SYAN" SPC02SYAN 98.47,45.413 r180 top value=1x2
T1 "CXS70-14-C" Panduit_CXS70-14-C 12.954,57.785 r0 top
T2 "CXS70-14-C" Panduit_CXS70-14-C 12.954,32.385 r0 top
T3 "CXS70-14-C" Panduit_CXS70-14-C 141.986,57.785 r180 top
T4 "CXS70-14-C" Panduit_CXS70-14-C 141.986,32.385 r180 top
TP1 "RCU-0C" TE_RCU 83.185,29.464 r0 top
TP2 "RCU-0C" TE_RCU 83.185,60.071 r0 top
TP3 "RCU-0C" TE_RCU 77.075,40.13 r180 top
TP4 "RCU-0C" TE_RCU 77.018,50.038 r180 top
TP5 "5006" Keystone5006 101.391,40.475 r0 top
U1 "LM5125QRHBRQ1" RHB0032U-MFG 64.999,45.085 r90 top
ZZ2 "These assemblies are ESD sensitive, ESD precautions shall be observed." AssemblyNote 4.699,107.95 r0 top
ZZ3 "These assemblies must be clean and free from flux and all contaminants. Use of no clean flux is not acceptable." AssemblyNote 4.699,110.49 r0 top
ZZ4 "These assemblies must comply with workmanship standards IPC-A-610 Class 2, unless otherwise specified." AssemblyNote 4.699,113.03 r0 top
ZZ5 "Install Shunt Jumper SH-JP1 onto JP1 pins 1-2" AssemblyNote 4.699,115.57 r0 top
ZZ6 "Install Shunt Jumper SH-JP2 onto JP2 pins 1-2" AssemblyNote 4.699,118.11 r0 top
ZZ7 "Install Shunt Jumper SH-JP3 onto JP3 pins 2-3" AssemblyNote 4.699,120.65 r0 top
ZZ8 "Install Shunt Jumper SH-JP4 onto JP4" AssemblyNote 4.699,123.19 r0 top
ZZ9 "Install Shunt Jumper SH-JP5 onto JP5" AssemblyNote 4.801,125.5 r0 top
ZZ10 "Install Shunt Jumper SH-JP6 onto JP6" AssemblyNote 4.801,127.75 r0 top

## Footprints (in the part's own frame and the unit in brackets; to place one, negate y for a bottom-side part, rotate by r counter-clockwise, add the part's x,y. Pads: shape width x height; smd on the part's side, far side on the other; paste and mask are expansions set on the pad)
0402S [mil] "Based on C0402S footprint from PADS legacy"
  rect 15x24 smd: 1(-20,0) 2(20,0)
  body extent -22,-12 22,12, height 24
0603S [mil]
  rect 20x35 smd: 1(-30,0) 2(30,0)
  body extent -34,-19 34,19, height 39
0805L [mm] "0805 from SM-752 data"
  rect 1.1x1.4 smd: 1(-0.75,0) 2(0.75,0)
  body extent -1.1,-0.72 1.1,0.72, height 1.45
1206L [mm] "1206 from SM-752 data"
  rect 1.1x1.75 smd: 1(-1.35,0) 2(1.35,0)
  silkscreen extent -0.4,-0.77 0.4,0.77, body extent -1.7,-0.9 1.7,0.9, height 1.35
2512_WIDE [mm] "Ohmite recommended land pattern"
  rect 1x6.6 smd: 1(-1.6,0) 2(1.6,0)
  silkscreen extent -0.82,-3.32 0.82,3.35, body extent -1.65,-3.25 1.65,3.25, height 0.7
AssemblyNote [mm] "Assembly Note"
CONN_2510-6002 [mm] "3M 2500 series TS-0770-L December 15, 2011"
  rect 1.65x1.65 hole 1.016 mask+0: 1(-5.08,-1.27)
  round 1.65 hole 1.016 mask+0: 2(-5.08,1.27) 3(-2.54,-1.27) 4(-2.54,1.27) 5(0,-1.27) 6(0,1.27) 7(2.54,-1.27) 8(2.54,1.27) 9(5.08,-1.27) 10(5.08,1.27)
  silkscreen extent -10.01,-4.17 10.01,4.47, body extent -10.01,-4.11 10.01,4.52, height 9.92
Fiducial10-20 [mm]
  round 1 smd mask+0.5: 1(0,0)
  Top Layer keep-out circle w1.178: c0,0 r0.5
FP-EEHZU1H221P_RADIAL_SMT-MFG [mm]
  rrect5% 4.1x2 smd paste+0 mask+0: 1(-4.35,0) 2(4.35,0)
  silkscreen extent -7.07,-5.25 5.25,5.25, body extent -6.65,-5.5 6.65,5.5, height 0.25
FP-EEHZU1J151P_RADIAL_SMT-MFG [mm]
  rrect5% 4.1x2 smd paste+0 mask+0: 1(-4.35,0) 2(4.35,0)
  silkscreen extent -7.07,-5.25 5.25,5.25, body extent -6.65,-5.5 6.65,5.5, height 0.25
FP-GRM32EC72A106KE05L_1210-MFG [mm]
  rrect9% 1.1x2.05 smd paste+0 mask+0: 1(-1.65,0) 2(1.65,0)
  silkscreen extent -0.72,-1.35 0.72,1.35, body extent -2.3,-1.45 2.3,1.45, height 0.25
FP-WSL080500000ZEA9_0805-MFG [mm]
  rrect10% 1.02x1.27 smd paste+0 mask+0: 1(-0.76,0) 2(0.76,0)
  silkscreen extent -1.14,-1.05 1.14,1.05, body extent -1.37,-0.86 1.37,0.86, height 0.25
IEC_HotSurface_Small [mm]
  silkscreen extent -2.72,-2.36 2.72,2.35
IHLP-6767GZ [mm] "SMD, 2-Leads, Body 17.15x17.15mm"
  rrect3% 3.825x12.32 smd: 1(-8.123,0) 2(8.123,0)
  silkscreen extent -8.64,-8.57 8.64,8.57, body extent -8.59,-8.59 8.59,8.59, height 6.9
Johnson_108-0740-001 [mm] "Banana Jack Uninsulated Standard Type"
  round 12 hole 6.858: 1(0,0)
  body extent -4.77,-5.43 4.75,5.57, height 2.39
Keystone5006 [mil] "Keystone Compact loops"
  round 87 hole 63: 1(0,0)
  silkscreen extent -70,-70 70,70, body extent -63,-63 62,63, height 225
Keystone_1902C [mil] "Hex Standoff, 4-40 threaded, nylon"
  round 1 on Mech4: 0(0,0)
  body extent -145,-126 146,126, height 501
Net-Tie_10milWide_30milLong [mil] "10mil net tie, no solder mask opening, no solder paste"
  rect 30x10 smd paste-5 mask-5: 1(-15,0) 2(15,0)
"NY PMS 440 0025 PH" [mm] "4-40 nylon screw and mounting hole"
  round 8 hole 3.2: 1(0,0)
  body extent -3.3,-3.3 3.3,3.3, height 2.69
Panduit_CXS70-14-C [mil] "Panduit"
  rect 770x500 hole 270 copper offset -74.8,0 paste-99999: 1(0,0)
  body extent -960,-250 310,250, height 684
RHB0032U-MFG [mm]
  rrect40% 0.6x0.25 smd paste+0 mask+0: 1(-2.4,1.75) 2(-2.4,1.25) 3(-2.4,0.75) 4(-2.4,0.25) 5(-2.4,-0.25) 6(-2.4,-0.75) 7(-2.4,-1.25) 8(-2.4,-1.75) 17(2.4,-1.75) 18(2.4,-1.25) 19(2.4,-0.75) 20(2.4,-0.25) 21(2.4,0.25) 22(2.4,0.75) 23(2.4,1.25) 24(2.4,1.75)
  rrect40% 0.25x0.6 smd paste+0 mask+0: 9(-1.75,-2.4) 10(-1.25,-2.4) 11(-0.75,-2.4) 12(-0.25,-2.4) 13(0.25,-2.4) 14(0.75,-2.4) 15(1.25,-2.4) 16(1.75,-2.4) 25(1.75,2.4) 26(1.25,2.4) 27(0.75,2.4) 28(0.25,2.4) 29(-0.25,2.4) 30(-0.75,2.4) 31(-1.25,2.4) 32(-1.75,2.4)
  rrect3% 3.7x3.7 smd paste-1000 mask+0: 33(0,0)
  silkscreen extent -3.37,-2.55 2.55,2.55, body extent -2.8,-2.8 2.8,2.8, height 0.25
SO-8FL [mm] "ON SEMICONDUCTOR, DFN5 5x6, 1.27P, CASE 488AA"
  rect 1x0.75 smd: 1(-2.795,1.905) 2(-2.795,0.635) 3(-2.795,-0.635) 4(-2.795,-1.905)
  rect 4.055x4.56 smd: 5(0.698,0)
  Top Layer region: 3.2,-2.28 3.2,-1.53 2.65,-1.53 2.65,-2.28
  Top Layer region: 3.2,1.53 3.2,2.28 2.655,2.28 2.655,1.53
  Top Layer region: 0,-2.775 0,2.775 -0.905,2.775 -0.905,-2.775
  silkscreen extent -3.1,-2.6 3.1,2.9, body extent -3.17,-2.67 3.17,2.67, height 1.11
SPC02SYAN [mil] "SULLINS"
  round 1 on Mech3: 0(0,0)
  body extent -98,-47 99,47, height 366
SW_218-8LP [mm] "SMD, 16-Leads, Body 11.33x5.8mm, Pitch 1.27mm"
  rect 1.27x0.76 smd: 1(-3.81,4.445) 2(-3.81,3.175) 3(-3.81,1.905) 4(-3.81,0.635) 5(-3.81,-0.635) 6(-3.81,-1.905) 7(-3.81,-3.175) 8(-3.81,-4.445) 9(3.81,-4.445) 10(3.81,-3.175) 11(3.81,-1.905) 12(3.81,-0.635) 13(3.81,0.635) 14(3.81,1.905) 15(3.81,3.175) 16(3.81,4.445)
  silkscreen extent -2.9,-5.67 2.9,5.9, body extent -4.22,-5.66 4.22,5.66, height 2.62
TE_RCU [mm] "SMD, 1-Leads, Body 1.6x0.8mm"
  rrect8% 2.4x1.2 smd: 1(0,0)
  body extent -0.8,-0.45 0.8,0.45, height 1.15
TO-277A [mm] "Vishay"
  rect 1.4x1.27 smd: 1(-1.04,1.83) 2(1.04,1.83)
  rect 4.72x4.8 smd: 3(0,-1.883)
  silkscreen extent -2.7,1.45 -2.4,1.75, body extent -2.35,-4.2 2.4,2.45, height 1.2
TSW-112-07-G-D [mm] "Samtec 100mil, 2x12, 230 mil above insulator"
  rrect6% 1.65x1.65 hole 1.016: 1(-13.97,-1.27)
  round 1.65 hole 1.016: 2(-13.97,1.27) 3(-11.43,-1.27) 4(-11.43,1.27) 5(-8.89,-1.27) 6(-8.89,1.27) 7(-6.35,-1.27) 8(-6.35,1.27) 9(-3.81,-1.27) 10(-3.81,1.27) 11(-1.27,-1.27) 12(-1.27,1.27) 13(1.27,-1.27) 14(1.27,1.27) 15(3.81,-1.27) 16(3.81,1.27) 17(6.35,-1.27) 18(6.35,1.27) 19(8.89,-1.27) 20(8.89,1.27) 21(11.43,-1.27) 22(11.43,1.27) 23(13.97,-1.27) 24(13.97,1.27)
  silkscreen extent -16.27,-2.54 15.24,2.54, body extent -15.24,-2.54 15.24,2.54, height 8.38
WURTH_61300111121 [mm] "Header, 2.54 mm, 1x1, TH"
  rect 1.65x1.65 hole 1.15: 1(0,0)
  silkscreen extent -1.27,-1.27 1.27,1.27, body extent -1.27,-1.27 1.27,1.27, height 8.54
WURTH_61300211121 [mm] "Header, 2.54mm, 2x1, TH"
  rrect50% 1.65x1.65 hole 1.15: 1(-1.27,0)
  round 1.65 hole 1.15: 2(1.27,0)
  body extent -2.54,-1.27 2.54,1.27, height 8.54
WURTH_61300311121 [mm] "Header, 2.54mm, 3x1, TH"
  rrect50% 1.65x1.65 hole 1.15: 1(-2.54,0)
  round 1.65 hole 1.15: 2(0,0) 3(2.54,0)
  body extent -3.81,-1.27 3.81,1.27, height 8.54

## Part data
C1 C3 C13 C14 C15 C29 C30 C41 C42 C43 C44 C45 C46 C47 C48 C49 C50 C51 C52 C53 C54 C55 C56 C57 C58 C59 C60 C69: library part CMP-0007469-4, "CAP, CERM, 0.1 uF, 100 V, +/- 10%, X7R, 0603", Cap_Case=0603, Manufacturer=MuRata, Supplier Part Number 1=490-3285-1-ND, TempCo=X7R, Tolerance_%=10%, Value1=Unknown, Value2=100V, ValueDisplayed=0.1uF
C2: library part CMP-0086249-1, "CAP, CERM, 1 µF, 50 V,+/- 10%, X7R, AEC-Q200 Grade 1, 0805", Cap_Case=0805, Manufacturer=MuRata, TempCo=X7R, Tolerance_%=10%, Value2=50V, ValueDisplayed=1µF
C4: library part CMP-0079153-1, "CAP, CERM, 10 µF, 10 V,+/- 10%, X7R, AEC-Q200 Grade 1, 0805", Cap_Case=0805, Manufacturer=MuRata, Supplier Part Number 1=490-12646-1-ND, TempCo=X7R, Tolerance_%=10%, Value2=10V, ValueDisplayed=10µF
C5: library part CMP-0007147-5, "CAP, CERM, 0.015 uF, 100 V, +/- 10%, X7R, AEC-Q200 Grade 1, 0603", Cap_Case=0603, Manufacturer=MuRata, Supplier Part Number 1=490-8029-1-ND, TempCo=X7R, Tolerance_%=10%, Value1=Unknown, Value2=100V, ValueDisplayed=0.015uF
C6: library part CMP-0007064-4, "CAP, CERM, 500 pF, 50 V, +/- 5%, C0G/NP0, 0603", Cap_Case=0603, Manufacturer="Yageo America", Supplier Part Number 1=CC0603JRNPO9BN501-ND, TempCo=C0G/NP0, Tolerance_%=5%, Value1=Unknown, Value2=50V, ValueDisplayed=500pF
C7: library part CMP-0006988-4, "CAP, CERM, 10 pF, 50 V, +/- 5%, C0G/NP0, 0603", Cap_Case=0603, Manufacturer=TDK, Supplier Part Number 1=445-1269-1-ND, TempCo=C0G/NP0, Tolerance_%=5%, Value1="0.3492 ohm", Value2=50V, ValueDisplayed=10pF
C8: library part CMP-0006925-5, "CAP, CERM, 0.33 uF, 10 V, +/- 10%, X5R, 0603", Cap_Case=0603, Manufacturer=Kemet, Supplier Part Number 1=399-3112-1-ND, TempCo=X5R, Tolerance_%=10%, Value1=Unknown, Value2=10V, ValueDisplayed=0.33uF
C9 C10: library part CMP-0006960-4, "CAP, CERM, 680 pF, 50 V, +/- 10%, X7R, 0603", Cap_Case=0603, Manufacturer=Kemet, Supplier Part Number 1=399-1077-1-ND, TempCo=X7R, Tolerance_%=10%, Value1=Unknown, Value2=50V, ValueDisplayed=680pF
C11 C12: library part CMP-0085815-1, "CAP, CERM, 68 pF, 50 V,+/- 1%, C0G/NP0, 0402", Cap_Case=0402, Manufacturer=AVX, TempCo=C0G/NP0, Tolerance_%=1%, Value2=50V, ValueDisplayed=68pF
C16: library part CMP-0007868-2, "CAP, CERM, 3.3 uF, 25 V, +/- 10%, X7R, 0805", Cap_Case=0805, Manufacturer=TDK, Supplier Part Number 1=445-5970-1-ND, TempCo=X7R, Tolerance_%=10%, Value1=Unknown, Value2=25V, ValueDisplayed=3.3uF
C17: library part CMP-0006989-4, "CAP, CERM, 100 pF, 50 V, +/- 5%, C0G/NP0, 0603", Cap_Case=0603, Manufacturer=TDK, Supplier Part Number 1=445-173611-1-ND, TempCo=C0G/NP0, Tolerance_%=5%, Value1=Unknown, Value2=50V, ValueDisplayed=100pF
C18 C19: library part CMP-0007049-4, "CAP, CERM, 0.047 uF, 50 V, +/- 10%, X7R, 0603", Cap_Case=0603, Manufacturer=TDK, Supplier Part Number 1=445-1313-1-ND, TempCo=X7R, Tolerance_%=10%, Value1="0.049007 ohm", Value2=50V, ValueDisplayed=0.047uF
C20: library part CMP-0007969-2, "CAP, CERM, 0.1 uF, 100 V, +/- 10%, X7R, AEC-Q200 Grade 1, 0805", Cap_Case=0805, Manufacturer=TDK, Supplier Part Number 1=445-5827-1-ND, TempCo=X7R, Tolerance_%=10%, Value1="0.020726 ohm", Value2=100V, ValueDisplayed=0.1uF
C21 C22 C23 C24 C31 C32 C33 C34 C35 C36 C37 C38 C39 C40: library part CMP-0087970-1, "10µF ±10% 100V Ceramic Capacitor X7S 1210 (3225 Metric)", Manufacturer=Murata, TempCo=22%, Tolerance_%=10%, ValueDisplayed=10uF
C25 C26 C27 C28: library part CMP-0120360-1, "Aluminum Hybrid Polymer Capacitors 220uF 20% 50V Life 4000Hours AEC-Q200 RADIAL SMT", Leakage Current=110uA, Manufacturer=Panasonic, Operating Temperature Range="-55°C to +135°C", Tolerance_%=20%, ValueDisplayed=220uF
C61 C62 C63 C64 C65 C66 C67 C68: library part CMP-0120392-1, "Aluminum Hybrid Polymer Capacitors 150uF 20% 63V Life 4000Hours AEC-Q200 RADIAL SMT", Leakage Current=94.5uA, Manufacturer=Panasonic, Operating Temperature Range="-55°C to +135°C", Tolerance_%=20%, ValueDisplayed=150uF
D1 D2 D3 D4: library part CMP-0028832-2, "Diode, Schottky, 100 V, 12 A, AEC-Q101, TO-277A", Manufacturer=Vishay-Semiconductor, Value1=12A, Value2=0.7V
FID1 FID2 FID3: library part CMP-0077181-1, "Fiducial mark.  There is nothing to buy or mount.", Manufacturer=N/A
H1 H2 H3 H4: library part CMP-0003617-1, "Machine Screw, Round, #4-40 x 1/4, Nylon, Philips panhead", Manufacturer="B&F Fastener Supply", Supplier Part Number 1=H542-ND
H5 H6 H7 H8: library part CMP-0003610-1, "Standoff, Hex, 0.5\"L #4-40 Nylon", Manufacturer=Keystone, Supplier Part Number 1=36-1902C-ND
J1 J2 J3 J4: library part CMP-0055387-2, "Standard Banana Jack, Uninsulated, 15A", Manufacturer="Cinch Connectivity", Supplier Part Number 1=J147-ND
J5 J6 J7 J8 J11 J12 JP4 JP5 JP6: library part CMP-0054794-2, "Header, 2.54 mm, 2x1, Gold, TH", Color=Black, Manufacturer="Wurth Elektronik", Supplier Part Number 1=732-5315-ND
J9 J10: library part CMP-0075423-1, "Header, 100mil, 12x2, Gold, TH", Color=Black, Current_A=6.3A, Manufacturer=Samtec, Supplier Part Number 1=SAM1028-12-ND, Voltage_V=550V
J13: library part CMP-0055448-2, "Header (shrouded), 100mil, 5x2, High-Temperature, Gold, TH", Manufacturer=3M, PartNumber=N2510-6002-RB, Supplier Part Number 1=MHC10K-ND
J14: library part CMP-0054792-1, "Header, 2.54 mm, 1x1, Gold, TH", Manufacturer="Wurth Elektronik", Supplier Part Number 1=732-5314-ND
JP1 JP2 JP3: library part CMP-0054796-4, "Header, 2.54 mm, 3x1, Gold, TH", Manufacturer="Wurth Elektronik", Supplier Part Number 1=732-5316-ND
L1 L2: library part CMP-0750174-1, "Inductor, Shielded, 3.3 µH, 32.2 A, 0.00327 ohm, AEC-Q200 Grade 0, SMD", Manufacturer=Vishay-Dale, Value1="0.00327 ohm", Value2=32.2A, ValueDisplayed=3.3µH
Logo5 Logo6: library part CMP-0074837-2, "IEC 61010-1 Hot Surface Warning", Manufacturer="Texas Instruments"
NT1: library part CMP-0078142-6, "Single point connection between nets.", Manufacturer=N/A
Q1 Q2 Q3 Q4 Q5 Q6 Q7 Q8: library part CMP-0000853-1, "MOSFET, N-CH, 60 V, 71 A, SO-8FL", Alternate Manufacturer=None, Manufacturer="ON Semiconductor", PartNumber=NTMFS5C670NLT1G, Supplier Part Number 1=NTMFS5C670NLT1GOSCT-ND, Value1=0.008, Value2="20 nC"
R1 R2 R3 R4: library part CMP-0084409-1, "RES, 0.0015, 5%, 2 W, 2512 WIDE", Manufacturer=Rohm, Power_W=2W, TempCo="100 ppm/C", Tolerance_%=5%, Value_Code=1L500, ValueDisplayed=0.0015
R5: library part CMP-0022204-4, "RES, 20.0 k, 1%, 0.1 W, AEC-Q200 Grade 0, 0603", Manufacturer=Vishay-Dale, Power_W=100mW, Supplier Part Number 1=541-20.0KHCT-ND, TempCo="100 ppm/C", Tolerance_%=1%, Value2=0.1W, Value_Code=20k0, ValueDisplayed=20.0k
R6: library part CMP-0024471-3, "RES, 78.7 k, 0.1%, 0.1 W, 0603", Manufacturer="Yageo America", Power_W=100mW, TempCo="25 ppm/C", Tolerance_%=0.1%, Value2=0.1W, Value_Code=78k7, ValueDisplayed=78.7k
R7: library part CMP-0026395-2, "RES, 47.5 k, 1%, 0.063 W, AEC-Q200 Grade 0, 0402", Manufacturer=Vishay-Dale, Power_W=63mW, Supplier Part Number 1=541-47.5KLCT-ND, TempCo="100 ppm/C", Tolerance_%=1%, Value2=0.063W, Value_Code=47k5, ValueDisplayed=47.5k
R8: library part CMP-0022558-4, "RES, 6.04 k, 1%, 0.1 W, AEC-Q200 Grade 0, 0603", Manufacturer=Vishay-Dale, Power_W=100mW, Supplier Part Number 1=541-6.04KHCT-ND, TempCo="100 ppm/C", Tolerance_%=1%, Value2=0.1W, Value_Code=6k04, ValueDisplayed=6.04k
R9 R94: library part CMP-0021424-3, "RES, 75.0 k, 1%, 0.125 W, AEC-Q200 Grade 0, 0805", Manufacturer=Vishay-Dale, Power_W=125mW, Supplier Part Number 1=541-75.0KCCT-ND, TempCo="100 ppm/C", Tolerance_%=1%, Value2=0.125W, Value_Code=75k0, ValueDisplayed=75.0k
R10: library part CMP-0020536-3, "RES, 39 k, 5%, 0.125 W, AEC-Q200 Grade 0, 0805", Manufacturer=Vishay-Dale, Power_W=125mW, Supplier Part Number 1=541-39KACT-ND, TempCo="200 ppm/C", Tolerance_%=5%, Value2=0.125W, Value_Code=39k0, ValueDisplayed=39k
R11 R12 R13 R14: library part CMP-0122265-1, "0 Ohms Jumper Chip Resistor 0805 (2012 Metric) Metal Element", Digikey Part Number=541-3928-1-ND, Manufacturer=Vishay, Mouser Part Number=71-WSL080500000ZEA9, Operating Temperature Range="-65°C to +170°C", Power_W=125mW, TempCo=3900ppm/°C
R15 R16 R17 R18 R39 R40 R41 R57 R73: library part CMP-0023343-3, "RES, 0, 1%, 0.1 W, AEC-Q200 Grade 0, 0603", Manufacturer="Stackpole Electronics Inc", Power_W=100mW, Supplier Part Number 1=RMCF0603ZT0R00CT-ND, TempCo=ppm/C, Tolerance_%=1%, Value2=0.1W, Value_Code=0
R19: library part CMP-0021990-4, "RES, 100 k, 1%, 0.1 W, AEC-Q200 Grade 0, 0603", Manufacturer=Vishay-Dale, Power_W=100mW, Supplier Part Number 1=541-100KHCT-ND, TempCo="100 ppm/C", Tolerance_%=1%, Value2=0.1W, Value_Code=100k
R20 R22 R24 R26 R28: library part CMP-0022003-4, "RES, 10.0, 1%, 0.1 W, AEC-Q200 Grade 0, 0603", Manufacturer=Vishay-Dale, Power_W=100mW, Supplier Part Number 1=541-10.0HCT-ND, TempCo="100 ppm/C", Tolerance_%=1%, Value2=0.1W, Value_Code=10R0, ValueDisplayed=10.0
R21 R23 R25 R27: library part CMP-0022711-2, "RES, 2.20, 1%, 0.1 W, 0603", Manufacturer=Panasonic, Power_W=100mW, Supplier Part Number 1=P2.2AJCT-ND, TempCo="200 ppm/C", Tolerance_%=1%, Value2=0.1W, Value_Code=2R20, ValueDisplayed=2.20
R29 R30: library part CMP-0016971-3, "RES, 3.24, 1%, 0.25 W, AEC-Q200 Grade 0, 1206", Manufacturer=Vishay-Dale, Power_W=250mW, Supplier Part Number 1=541-3.24FFCT-ND, TempCo="100 ppm/C", Tolerance_%=1%, Value2=0.25W, Value_Code=3R24, ValueDisplayed=3.24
